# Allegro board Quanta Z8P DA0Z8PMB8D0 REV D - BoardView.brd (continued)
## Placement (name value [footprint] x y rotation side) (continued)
PQ4  AO3404  [SOT23_213-3_3-2]  48.25 89.11 90 top
PQ5  2N7002K  [SOT23_213-3_3-2]  35.24 75.34 90 top
PQ6  TPCA8109  [POWER-5X5-1_27-5P]  233.41 40.21 180 top
PQ7  2N7002K  [SOT23_213-3_3-2]  68.49 30.84 90 top
PQ8  2N7002K  [SOT23_213-3_3-2]  41.8 30 0 top
PQ9  2N7002KDW  [SOT363-2_1-65-6P]  38.43 24.94 180 top
PQ10  *2N7002K  [SOT23_213-3_3-2]  31.77 21.11 90 top
PQ11  AON7410  [DFN-8L-3X3-65-5P-0_9H]  75.81 131.53 270 bottom
PQ12  AON7752  [DFN-8L-3X3-65-5P-0_9H]  80.12 131.27 0 bottom
PQ13  AON6414AL  [POWER-5_2X5_55-1_27-5P]  89.57 131.2 0 bottom
PQ14  AON6752  [POWER-5_2X5_55-1_27-5P]  96.43 131.07 0 bottom
PQ15  *2N7002K  [SOT23_213-3_3-2]  149.9 43.5 180 bottom
PQ16  IMD2AT108  [SC74-2_8-95-6P]  201 37.79 270 bottom
PQ17  TPCA8109  [POWER-5X5-1_27-5P]  69.64 28.08 0 bottom
PQ18  AON7410  [DFN-8L-3X3-65-5P-0_9H]  95.74 28.02 180 bottom
PQ19  AON7752  [DFN-8L-3X3-65-5P-0_9H]  95.74 24.08 270 bottom
PQ20  AON7410  [DFN-8L-3X3-65-5P-0_9H]  51.42 23.07 270 bottom
PQ21  AON7410  [DFN-8L-3X3-65-5P-0_9H]  51.42 19.13 270 bottom
PQ22  VL@AO3415  [SOT23_213-3_3-2]  58.28 116.85 270 top
PQ23  VL@2N7002K  [SOT23_213-3_3-2]  62.22 120.22 0 top
PQ24  VL@DDTC144EUA-7-F  [UMT_213-3-1_3]  65.52 138.13 0 top
PQ25  VL@2N7002K  [SOT23_213-3_3-2]  61.71 137.88 0 top
PR1  *S_6  [S0603]  100.13 137.62 0 top
PR2  *S_6  [S0603]  82.28 137.01 0 top
PR3  100K_1%_4  [R0402]  129.27 135.77 270 top
PR4  *S_4  [S0402]  131.56 133.94 180 top
PR5  2.2_5%_6  [R0603]  96.25 132.8 180 top
PR6  2.61K_1%_4  [R0402]  116.42 130.65 90 top
PR7  VL@0_5%_4  [R0402]  51.43 129.78 90 top
PR8  VL@20K_1%_4  [R0402]  53.68 129.78 90 top
PR9  VL@174K_1%_4  [R0402]  54.7 129.78 270 top
PR10  VL@100K_5%_4  [R0402]  55.74 129.77 90 top
PR11  127K_1%_4  [R0402]  110.81 128.61 270 top
PR12  *S_4  [S0402]  113.96 128.61 270 top
PR13  402_1%_4  [R0402]  115.04 128.61 270 top
PR14  332_1%_4  [R0402]  117.46 128.61 270 top
PR15  *S_6  [S0603]  130.97 128.85 90 top
PR16  2.2_5%_6  [R0603]  74.92 127.59 0 top
PR17  *4.7_5%_6  [R0603]  127.47 127.36 90 top
PR18  63.4K_1%_4  [R0402]  118.86 126.32 180 top
PR19  11K_1%_4  [R0402]  107.54 125.94 0 top
PR20  63.4K_1%_4  [R0402]  118.86 125.18 180 top
PR21  100_1%_4  [R0402]  104 124.54 0 top
PR22  2.61K_1%_4  [R0402]  105.9 124.54 0 top
PR23  499_1%_4  [R0402]  109.59 124.54 0 top
PR24  20_1%_4  [R0402]  118.86 124.03 0 top
PR25  *VL@0_5%_4  [R0402]  57.3 124.2 0 top
PR26  2.55K_1%_4  [R0402]  107.68 123.4 0 top
PR27  169_1%_4  [R0402]  121.02 123.12 0 top
PR28  *VL@0_5%_4  [R0402]  58.67 123.4 270 top
PR29  VL@0_5%_4  [R0402]  57.3 123.24 180 top
PR30  100_1%_4  [R0402]  104.38 122.38 180 top
PR31  10K_1%_4  [R0402]  107.68 122.26 0 top
PR32  27.4K_1%_4  [R0402]  109.59 122.26 0 top
PR33  *S_4  [S0402]  118.86 120.6 180 top
PR35  1M_5%_6  [R0603]  138.8 89.24 0 top
PR36  1M_5%_6  [R0603]  141.59 89.24 180 top
PR37  1M_5%_6  [R0603]  144.39 89.24 180 top
PR38  *100K_1%_6  [R0603]  146.67 88.73 90 top
PR39  22_5%_8  [R0805]  41.01 87.33 270 top
PR40  *4.7_5%_6  [R0603]  140.52 82.35 0 top
PR41  *S_6  [S0603]  46.54 81.67 90 top
PR42  22_5%_8  [R0805]  33.5 72.87 270 top
PR43  *220_5%_8  [R0805]  145.4 40.98 180 top
PR44  0.02_1%_0612  [RC3216]  219.59 34.3 270 top
PR45  *S_4  [S0402]  219.16 31.42 270 top
PR46  *S_4  [S0402]  220.31 31.42 270 top
PR47  *S_4  [S0402]  102.35 31.32 270 top
PR48  100_1%_4  [R0402]  103.75 31.32 90 top
PR49  33K_1%_4  [R0402]  71.4 30.55 0 top
PR50  *100K_5%_4  [R0402]  44.85 30.39 270 top
PR51  10K_5%_4  [R0402]  70.24 29.38 0 top
PR52  *4.7_5%_6  [R0603]  91.51 27.92 0 top
PR53  *0_5%_4  [R0402]  107.43 27.21 0 top
PR54  51K_1%_4  [R0402]  41.8 27.08 90 top
PR55  *S_4  [S0402]  42.95 27.08 90 top
PR56  *10K_5%_4  [R0402]  40.49 26.8 90 top
PR57  *0_5%_4  [R0402]  38.96 26.75 180 top
PR58  20_5%_12  [R1206]  48.03 25.59 90 top
PR59  *S_4  [S0402]  108.34 25.35 270 top
PR60  100K_5%_4  [R0402]  40.53 24.92 270 top
PR61  100K_5%_4  [R0402]  41.8 24.92 90 top
PR62  10K_5%_4  [R0402]  42.87 24.92 270 top
PR63  100K_5%_4  [R0402]  36.5 24.31 90 top
PR64  *S_4  [S0402]  104.51 24.08 90 top
PR65  *S_4  [S0402]  105.65 24.08 90 top
PR66  *0_5%_4  [R0402]  42.57 23.4 180 top
PR67  63.4K_1%_4  [R0402]  39.52 22.64 90 top
PR68  11K_1%_4  [R0402]  40.66 22.64 90 top
PR69  *4.7_5%_6  [R0603]  54.72 20.78 180 top
PR70  *S_4  [S0402]  39.62 20.1 180 top
PR71  *S_6  [S0603]  37.61 19.72 90 top
PR72  *S_6  [S0603]  48.03 19.24 180 top
PR73  100_1%_4  [R0402]  73.77 19.13 90 top
PR74  100_1%_4  [R0402]  74.92 19.13 90 top
PR75  100_1%_4  [R0402]  79.11 19.13 90 top
PR76  *S_4  [S0402]  39.62 19.08 180 top
PR77  *0_5%_4  [R0402]  72.12 19 270 top
PR78  0.01_1%_0612  [RC3216]  62.54 18.12 90 top
PR79  1M_5%_4  [R0402]  73.77 17.23 90 top
PR80  316K_1%_4  [R0402]  39.86 16.06 90 top
PR81  10K_5%_4  [R0402]  41.02 16.17 90 top
PR82  *S_4  [S0402]  63.15 15.06 90 top
PR83  *S_4  [S0402]  62.01 15.04 90 top
PR84  *S_4  [S0402]  93.08 137.33 0 bottom
PR85  *S_4  [S0402]  76.44 136.86 0 bottom
PR86  *S_6  [S0603]  92.67 136.12 0 bottom
PR87  *S_4  [S0402]  129.27 135.77 270 bottom
PR88  10K_1%_4  [R0402]  130.26 135.77 90 bottom
PR89  *S_4  [S0402]  81.88 135.64 180 bottom
PR90  *S_4  [S0402]  99.12 135.34 180 bottom
PR91  3.65K_1%_6  [R0603]  113.1 134.18 0 bottom
PR92  *S_6  [S0603]  76.49 134.93 90 bottom
PR93  499K_1%_4  [R0402]  131.25 134.93 90 bottom
PR94  *S_6  [S0603]  113.12 132.77 0 bottom
PR95  100_1%_4  [R0402]  115.16 132.73 90 bottom
PR96  *S_4  [S0402]  116.95 132.42 0 bottom
PR97  *S_4  [S0402]  118.73 132.42 0 bottom
PR98  150K_1%_4  [R0402]  131.56 133.43 180 bottom
PR99  1K_1%_4  [R0402]  131.56 132.29 0 bottom
PR100  11K_1%_4  [R0402]  116.42 130.65 90 bottom
PR101  1K_1%_4  [R0402]  117.46 130.65 270 bottom
PR102  *S_6  [S0603]  122.03 128.73 180 bottom
PR103  *S_4  [S0402]  110.81 128.61 90 bottom
PR104  *S_4  [S0402]  111.82 128.61 90 bottom
PR105  4.02K_1%_4  [R0402]  112.84 128.61 270 bottom
PR106  *2K_1%_4  [R0402]  113.96 128.61 270 bottom
PR107  301_1%_4  [R0402]  115.04 128.61 270 bottom
PR108  *S_4  [S0402]  118.86 127.34 0 bottom
PR109  10K_1%_4  [R0402]  131.18 128.1 180 bottom
PR110  10K_NTC_4_1%  [R0402]  82.28 127.84 180 bottom
PR111  182_1%_4  [R0402]  109.59 127.08 0 bottom
PR112  *S_4  [S0402]  118.86 126.32 0 bottom
PR113  470K_NTC_4_5%  [R0402]  99.55 126.95 0 bottom
PR114  *S_6  [S0603]  121.4 126.07 180 bottom
PR115  1K_1%_4  [R0402]  107.54 125.94 0 bottom
PR116  10K_NTC_4_1%  [R0402]  99.55 125.43 0 bottom
PR117  1_1%_6  [R0603]  121.37 124.56 0 bottom
PR118  2K_1%_4  [R0402]  109.59 124.54 0 bottom
PR119  *S_4  [S0402]  104.38 123.53 180 bottom
PR120  2K_1%_4  [R0402]  109.59 123.4 0 bottom
PR121  3.65K_1%_6  [R0603]  99.68 124.03 0 bottom
PR122  86.6_1%_4  [R0402]  121.02 123.12 0 bottom
PR123  95.3_1%_4  [R0402]  118.86 122.71 180 bottom
PR124  *S_4  [S0402]  104.38 122.38 180 bottom
PR125  *S_4  [S0402]  131.18 122.64 180 bottom
PR126  *S_6  [S0603]  99.68 122.59 0 bottom
PR127  *S_4  [S0402]  118.86 121.75 180 bottom
PR128  97.6K_1%_4  [R0402]  109.59 121.11 0 bottom
PR129  10K_1%_4  [R0402]  121.02 120.73 0 bottom
PR130  *S_4  [S0402]  118.86 120.6 180 bottom
PR131  *10K_1%_4  [R0402]  119.24 119.59 0 bottom
PR132  *S_4  [S0402]  113.55 119.46 180 bottom
PR133  *S_4  [S0402]  117.33 119.59 180 bottom
PR136  *S_4  [S0402]  123.32 115.55 180 bottom
PR137  *S_4  [S0402]  123.32 114.43 180 bottom
PR138  *S_4  [S0402]  123.32 113.37 0 bottom
PR141  7.5K_1%_4  [R0402]  130.03 111.13 90 bottom
PR142  *S_4  [S0402]  126.61 110.75 0 bottom
PR143  10K_1%_4  [R0402]  128.51 109.73 0 bottom
PR144  100K_1%_4  [R0402]  124.09 108.41 270 bottom
PR145  *S_4  [S0402]  125.11 108.41 270 bottom
PR146  *S_4  [S0402]  118.13 108.16 180 bottom
PR147  10_5%_6  [R0603]  130.8 106 270 bottom
PR148  *2.2_5%_6  [R0603]  126.22 104.22 90 bottom
PR149  100K_1%_4  [R0402]  131.69 92.16 90 bottom
PR150  *S_6  [S0603]  130.42 90.76 90 bottom
PR151  *S_4  [S0402]  133.46 90.76 90 bottom
PR152  *S_4  [S0402]  131.69 90.25 270 bottom
PR153  24K_1%_4  [R0402]  112.88 89.41 270 bottom
PR154  16K_1%_4  [R0402]  133.46 88.85 90 bottom
PR155  15K_1%_4  [R0402]  133.46 86.95 90 bottom
PR156  *S_4  [S0402]  119.93 85.44 180 bottom
PR157  *S_4  [S0402]  144.11 85.35 270 bottom
PR158  499K_1%_4  [R0402]  145.12 85.32 90 bottom
PR159  150_1%_4  [R0402]  117.83 84.22 270 bottom
PR160  100K_1%_4  [R0402]  46.97 84.1 90 bottom
PR161  *S_4  [S0402]  47.93 84.1 90 bottom
PR162  150K_1%_4  [R0402]  145.15 83.9 180 bottom
PR163  *S_4  [S0402]  132.32 83.14 90 bottom
PR164  *S_4  [S0402]  145.53 82.63 180 bottom
PR165  *S_4  [S0402]  46.97 82.2 270 bottom
PR166  30K_1%_4  [R0402]  47.93 82.2 90 bottom
PR167  15K_1%_4  [R0402]  48.89 82.2 270 bottom
PR168  1K_1%_4  [R0402]  145.53 81.49 0 bottom
PR169  *S_6  [S0603]  138.92 79.89 180 bottom
PR170  100K_5%_4  [R0402]  49.14 75.01 90 bottom
PR171  *S_4  [S0402]  145.15 69.55 180 bottom
PR172  *S_4  [S0402]  144.39 61.95 270 bottom
PR173  *S_4  [S0402]  145.4 61.95 270 bottom
PR174  *S_4  [S0402]  146.42 61.95 90 bottom
PR179  *S_4  [S0402]  137.92 51.12 180 bottom
PR180  *S_8  [S0805]  132.34 50.11 90 bottom
PR181  *S_8  [S0805]  146.37 48.75 270 bottom
PR182  *S_4  [S0402]  131.25 46.31 180 bottom
PR183  30K_1%_4  [R0402]  146.04 46.11 0 bottom
PR184  100K_5%_4  [R0402]  134.26 45.92 90 bottom
PR185  34K_1%_4  [R0402]  144.49 45.7 90 bottom
PR186  100K_5%_4  [R0402]  134.26 43.99 270 bottom
PR187  220K_1%_4  [R0402]  198.55 36.94 180 bottom
PR188  220K_1%_4  [R0402]  198.55 35.98 0 bottom
PR189  *S_4  [S0402]  201.39 34.9 180 bottom
PR190  *S_4  [S0402]  104.84 31.3 270 bottom
PR191  10K_1%_4  [R0402]  106.67 30.21 180 bottom
PR192  10K_1%_4  [R0402]  107.43 29.24 180 bottom
PR193  *S_4  [S0402]  107.43 28.28 0 bottom
PR194  499K_1%_4  [R0402]  107.43 27.21 0 bottom
PR195  2.2_5%_6  [R0603]  99.13 27.06 180 bottom
PR196  *S_4  [S0402]  107.43 25.87 0 bottom
PR197  100K_1%_4  [R0402]  107.82 24.53 270 bottom
PR198  *0_5%_4  [R0402]  105.65 24.08 90 bottom
PR199  340K_1%_4  [R0402]  103.36 24.08 90 bottom
PR200  100K_1%_4  [R0402]  39.55 17.93 180 bottom
PR201  *100K_5%_4  [R0402]  39.52 16.89 180 bottom
PR202  10_5%_6  [R0603]  43.42 15.83 270 bottom
PR203  7.5_5%_6  [R0603]  41.9 15.83 270 bottom
PR204  VL@0_5%_8  [R0805]  59.42 113.75 0 top
PR205  VL@100K_1%_4  [R0402]  56.88 113.24 0 top
PR206  VL@10K_5%_4  [R0402]  60.69 122.38 90 top
PR207  VL@0_5%_4  [R0402]  60.82 117.68 270 top
PR208  VL@0_5%_4  [R0402]  68.44 135.73 270 top
PR209  VL@1M_5%_6  [R0603]  66.79 135.08 270 top
PR210  VL@22_5%_8  [R0805]  61.58 134.83 0 top
PR211  VL@1M_5%_6  [R0603]  65.26 135.08 90 top
PR212  *VL@100K_1%_6  [R0603]  68.44 138.13 270 top
PU1  VL@TPS61087DRCR  [QFN10-3X3-5-16P]  53.08 126.42 180 top
PU2  BQ24737RGRR  [PVQFN20-3_5X3_5-5-25P]  43.2 19.97 180 top
PU3  ISL95808HRZ-T  [DFN8-2X2-5-9P-ISL6208BCRZ]  79.23 136.1 90 bottom
PU4  ISL95808HRZ-T  [DFN8-2X2-5-9P-ISL6208BCRZ]  96.13 135.89 90 bottom
PU5  SY8286BRAC  [QFN20-3X3-45-21P]  128.26 132.29 90 bottom
PU6  ISL95859AHRTZ-T  [QFN40-5X5-4-41P-ISL95859]  114.16 123.27 180 bottom
PU7  AOZ1331DI  [SON14-3X2-4-15P-SMT]  117.21 114.38 270 bottom
PU8  M5671RE1U  [DFN10-3X3-5-11P-G5318]  127.88 107.27 90 bottom
PU9  TMP708AIDBVR  [SOT23-5-2_8-95-5P-G708]  115.06 88.02 90 bottom
PU10  G5719CTB1U  [SOT23-6-2_8-95-6P-G5126TB1U]  131.18 86.57 270 bottom
PU11  SY8288CRAC  [QFN20-3X3-45-21P]  142.35 81.87 90 bottom
PU12  G5719CTB1U  [SOT23-6-2_8-95-6P-G5126TB1U]  46.14 78.84 270 bottom
PU13  AOZ1331DI  [SON14-3X2-4-15P-SMT]  145.02 55.96 0 bottom
PU14  G9661MF11U  [SOP8-6-1_27-9P-G5795F11U]  139.18 46.94 90 bottom
PU15  RT8231BGQW  [WQFN20-3X3-4-21P]  103.52 27.61 0 bottom
Q1  PJA138K  [SOT23_213-3_3-2]  65.09 131.65 180 top
Q2  DDTC144EUA-7-F  [UMT_213-3-1_3]  48.12 112.73 90 top
Q3  2N7002KDW  [SOT363-2_1-65-6P]  46.98 106.63 180 top
Q4  2N7002KDW  [SOT363-2_1-65-6P]  93.95 97.54 0 top
Q5  2N7002K  [SOT23_213-3_3-2]  60.82 85.81 180 top
Q6  TPC@PJA138K  [SOT23_213-3_3-2]  28.22 82.2 180 top
Q7  TPC@AON7401  [POWER-3_3X3_3-65-5P-SMT]  24.52 82.1 270 top
Q8  TPC@PJA138K  [SOT23_213-3_3-2]  28.22 78.49 90 top
Q9  PJA138K  [SOT23_213-3_3-2]  20.08 75.53 270 top
Q10  SSM6N43FU  [SC70-2_1-65-6P]  27.57 73.43 0 top
Q11  2N7002KDW  [SOT363-2_1-65-6P]  51.65 71.33 90 top
Q12  *PJA138K  [SOT23_213-3_3-2]  23.2 71.4 270 top
Q13  2N7002K  [SOT23_213-3_3-2]  18.41 57.63 180 top
Q14  YB8251ST23  [SOT23_213-3_3-2]  2.5 56 0 top
Q15  SSM6N43FU  [SC70-2_1-65-6P]  33.51 26.88 0 top
Q16  EJ@METR3904-G  [SOT23_213-3_3-2]  212.92 34.07 0 top
Q17  2N7002K  [SOT23_213-3_3-2]  129.59 33.76 270 top
Q19  GS@2N7002KDW  [SOT363-2_1-65-6P]  163.82 29.16 90 top
Q20  2N7002KDW  [SOT363-2_1-65-6P]  107.4 18.62 270 top
Q21  SSM6N43FU  [SC70-2_1-65-6P]  114.32 18.14 180 top
Q22  KBL@PJA3413  [SOT23_213-3_3-2]  230.24 17.35 0 top
Q23  KBL@DDTC144EUA-7-F  [UMT_213-3-1_3]  230.49 14.03 0 top
Q24  *SSM6N43FU  [SC70-2_1-65-6P]  105.14 108.41 90 bottom
Q25  *SSM6N43FU  [SC70-2_1-65-6P]  108.7 108.41 90 bottom
Q26  SSM6N43FU  [SC70-2_1-65-6P]  76.44 104.48 90 bottom
Q27  SSM6N43FU  [SC70-2_1-65-6P]  78.73 104.48 90 bottom
Q28  SSM6N43FU  [SC70-2_1-65-6P]  81.16 104.47 90 bottom
Q29  2N7002KDW  [SOT363-2_1-65-6P]  66.53 95.23 90 bottom
Q30  2N7002K  [SOT23_213-3_3-2]  53.09 88.48 180 bottom
Q31  PJA138K  [SOT23_213-3_3-2]  125.56 34.7 0 bottom
Q32  *PJA138K  [SOT23_213-3_3-2]  193.87 34.13 180 bottom
Q33  *SSM6N43FU  [SC70-2_1-65-6P]  131 32.31 0 bottom
Q34  EJ@PMST3904  [UMT_213-3-1_3]  193.82 23.17 90 bottom
Q35  *SSM6N43FU  [SC70-2_1-65-6P]  167.63 32.34 180 top
Q36  *PSD@SSM6N43FU  [SC70-2_1-65-6P]  30.75 96.5 90 top
R1  33_5%_4  [R0402]  60.31 132.29 90 top
R2  100K_5%_4  [R0402]  61.45 132.29 90 top
R3  0_5%_4  [R0402]  61.08 125.19 0 top
R4  *0_5%_4  [R0402]  61.08 124.23 0 top
R5  NVL@0_5%_6  [R0603]  53.07 114.38 90 top
R6  VL@0_5%_6  [R0603]  51.55 111.84 180 top
R7  10K_5%_4  [R0402]  47.61 108.41 0 top
R8  100K_5%_4  [R0402]  50.15 108.41 180 top
R9  *S_4  [S0402]  50.15 107.27 0 top
R10  *S_4  [S0402]  52.06 107.27 0 top
R11  10K_5%_4  [R0402]  43.42 107.02 270 top
R12  EJ@75_1%_8  [R0805]  27.69 105.87 90 top
R13  EJ@75_1%_8  [R0805]  30.23 105.87 90 top
R14  EJ@75_1%_8  [R0805]  34.07 105.87 90 top
R15  EJ@75_1%_8  [R0805]  36.69 105.87 90 top
R16  *4.7K_5%_4  [R0402]  74.59 101.65 0 top
R17  1K_1%_4  [R0402]  76.83 100.22 270 top
R18  *4.7K_5%_4  [R0402]  73.79 100.22 270 top
R19  *10K_5%_4  [R0402]  75.85 100.22 90 top
R20  4.7K_5%_4  [R0402]  74.8 100.22 90 top
R21  10K_5%_4  [R0402]  90.08 100.16 270 top
R22  10K_5%_4  [R0402]  91.85 100 0 top
R23  *10K_5%_4  [R0402]  80.02 99.87 270 top
R24  *S_4  [S0402]  81.09 99.86 270 top
R25  10K_5%_4  [R0402]  86.24 99.65 90 top
R26  *10K_5%_4  [R0402]  72.37 99.59 0 top
R27  *4.7K_5%_4  [R0402]  85.25 99.58 270 top
R28  *4.7K_5%_4  [R0402]  83.51 99.37 180 top
R29  4.7K_5%_4  [R0402]  72.36 98.57 180 top
R30  10K_5%_4  [R0402]  73.79 98.46 270 top
R31  10K_5%_4  [R0402]  79.62 98.27 0 top
R32  10K_5%_4  [R0402]  83.82 98.02 270 top
R33  10K_5%_4  [R0402]  85.28 97.83 270 top
R34  200_1%_4  [R0402]  89.43 97.59 90 top
R35  10K_5%_4  [R0402]  71.61 97.57 180 top
R36  4.7K_5%_4  [R0402]  79.39 97.31 0 top
R37  402_1%_4  [R0402]  100.55 97.14 180 top
R38  4.7K_5%_4  [R0402]  66.46 96.63 180 top
R39  4.7K_5%_4  [R0402]  71.61 96.55 0 top
R40  150_1%_4  [R0402]  96.45 96.14 180 top
R41  10K_5%_4  [R0402]  71.61 95.53 0 top
R42  60.4_1%_4  [R0402]  96.44 95.11 0 top
R43  10K_5%_4  [R0402]  71.61 94.52 0 top
R44  150_1%_4  [R0402]  93.64 94.41 180 top
R45  4.7K_5%_4  [R0402]  66.81 94.19 0 top
R47  *0_5%_4  [R0402]  25.29 93.71 0 top
R48  TPC@100K_1%_4  [R0402]  26.63 93.55 90 top
R49  *S_4  [S0402]  27.67 93.55 270 top
R50  TPC@100K_5%_4  [R0402]  28.69 93.55 90 top
R51  TPC@100K_5%_4  [R0402]  29.83 93.55 90 top
R52  33_5%_4  [R0402]  71.61 93.43 180 top
R54  10K_5%_4  [R0402]  87.44 92.44 270 top
R55  10K_5%_4  [R0402]  71.61 92.41 180 top
R56  TPC@10K_5%_4  [R0402]  30.29 92.05 0 top
R57  4.7K_5%_4  [R0402]  71.61 91.39 180 top
R58  200_1%_4  [R0402]  76.23 90.57 90 top
R59  10K_5%_4  [R0402]  71.61 90.38 180 top
R60  10M_5%_4  [R0402]  69.05 89.69 270 top
R61  10_5%_4  [R0402]  74.73 89.32 0 top
R62  330K_5%_4  [R0402]  82.88 88.08 180 top
R63  EC@20K_1%_4  [R0402]  54.35 87.62 180 top
R64  137_1%_4  [R0402]  98.96 86.82 180 top
R65  TPC@100K_5%_4  [R0402]  24.24 86.57 180 top
R66  10K_5%_4  [R0402]  58.41 86.19 90 top
R67  *100K_5%_4  [R0402]  67.4 86.14 180 top
R68  *S_4  [S0402]  30.96 86.06 270 top
R69  *TPC@100K_5%_4  [R0402]  31.92 86.06 270 top
R70  *10K_5%_4  [R0402]  32.88 86.06 270 top
R71  1K_1%_4  [R0402]  69.58 86.06 180 top
R72  10_5%_4  [R0402]  74.74 86.02 0 top
R73  200_1%_4  [R0402]  72.98 85.84 180 top
R74  402_1%_4  [R0402]  104.82 85.83 180 top
R75  113_1%_4  [R0402]  98.19 85.53 180 top
R76  TPC@100K_5%_4  [R0402]  24.46 85.18 270 top
R77  TPC@100K_5%_4  [R0402]  25.93 85.18 270 top
R78  *S_4  [S0402]  27.6 85.17 270 top
R79  *TPC@100K_5%_4  [R0402]  28.69 85.17 270 top
R80  TPC@100K_5%_4  [R0402]  29.65 85.17 270 top
R81  20K_1%_4  [R0402]  69.58 85.04 180 top
R82  *100K_5%_4  [R0402]  69.58 84.03 180 top
R83  10_5%_4  [R0402]  75.42 84.03 0 top
R84  *S_6  [S0603]  63.48 83.74 180 top
R85  10K_5%_4  [R0402]  69.58 83.01 0 top
R86  *S_6  [S0603]  67.17 82.34 270 top
R87  150_1%_4  [R0402]  102.53 82.11 180 top
R88  *S_4  [S0402]  69.58 82 180 top
R89  105_1%_4  [R0402]  90.15 81.79 180 top
R90  2K_1%_4  [R0402]  69.58 80.98 180 top
R91  105_1%_4  [R0402]  90.39 80.45 90 top
R92  2K_1%_4  [R0402]  69.58 79.96 180 top
R93  PSD@10K_5%_4  [R0402]  35.04 97.49 180 top
R94  TPC@100K_5%_4  [R0402]  25.23 79.51 180 top
R95  33_5%_4  [R0402]  69.58 78.95 180 top
R96  TPC@10K_5%_4  [R0402]  31 78.74 0 top
R97  TPC@10K_5%_4  [R0402]  25.23 78.55 180 top
R98  33_5%_4  [R0402]  69.58 77.78 180 top
R99  *S_4  [S0402]  21.35 77.3 270 top
R100  *0_5%_4  [R0402]  22.31 77.42 270 top
R101  10_5%_4  [R0402]  90.25 77 90 top
R102  10_5%_4  [R0402]  87.63 75.69 270 top
R103  *2.2K_5%_4  [R0402]  26.76 75.05 180 top
R104  *S_4  [S0402]  28.61 75.05 180 top
R105  1K_1%_4  [R0402]  91.27 74.9 270 top
R106  1K_1%_4  [R0402]  89.93 74.7 0 top
R107  *0_5%_4  [R0402]  19.58 72.09 270 top
R108  *S_4  [S0402]  20.83 72.09 270 top
R109  *0_5%_4  [R0402]  30.26 72.04 270 top
R110  2.2K_5%_4  [R0402]  17.77 71.97 90 top
R111  *0_5%_4  [R0402]  24.12 68.97 0 top
R112  *2.2K_5%_4  [R0402]  27.07 71.81 180 top
R113  *S_4  [S0402]  28.79 71.71 180 top
R114  *0_5%_4  [R0402]  19.58 70.31 270 top
R115  *S_4  [S0402]  20.83 70.31 270 top
R116  2.2K_5%_4  [R0402]  17.92 70.18 270 top
R117  *12.4K_1%_4  [R0402]  29.89 70.06 270 top
R118  *10K_5%_4  [R0402]  30.85 70.06 270 top
R119  *10K_5%_4  [R0402]  26.5 70.18 270 top
R120  *0_5%_4  [R0402]  27.46 70.05 270 top
R121  *0_5%_4  [R0402]  28.42 70.05 270 top
R122  470_1%_4  [R0402]  21.31 68.79 180 top
R123  *0_5%_4  [R0402]  19.12 68.71 180 top
R125  *0_5%_4  [R0402]  19.12 67.75 180 top
R126  470_1%_4  [R0402]  21.32 67.63 180 top
R129  470_1%_4  [R0402]  21.32 66.67 180 top
R130  *0_5%_4  [R0402]  19.12 66.55 180 top
R132  *0_5%_4  [R0402]  19.12 65.59 180 top
R133  470_1%_4  [R0402]  21.32 65.46 180 top
R134  470_1%_4  [R0402]  21.32 64.5 180 top
R135  *0_5%_4  [R0402]  19.12 64.38 180 top
R137  *0_5%_4  [R0402]  19.12 63.42 180 top
R138  470_1%_4  [R0402]  21.32 63.3 180 top
R139  470_1%_4  [R0402]  21.32 62.34 180 top
R140  *0_5%_4  [R0402]  19.12 62.21 180 top
R142  *0_5%_4  [R0402]  19.12 61.25 180 top
R143  470_1%_4  [R0402]  21.32 61.13 180 top
R144  3.65K_1%_4  [R0402]  47.87 59.64 0 top
R145  3.65K_1%_4  [R0402]  50.41 59.64 0 top
R146  3.65K_1%_4  [R0402]  47.87 58.63 180 top
R147  3.65K_1%_4  [R0402]  50.41 58.63 180 top
R148  3.65K_1%_4  [R0402]  118.35 56.6 180 top
R149  240_1%_4  [R0402]  64.91 56.52 90 top
R150  3.65K_1%_4  [R0402]  118.35 55.58 0 top
R151  2.2_5%_6  [R0603]  18.19 55.05 180 top
R152  1K_1%_4  [R0402]  50.41 54.56 180 top
R153  *S_4  [S0402]  22.85 52.94 180 top
R154  80.6_1%_4  [R0402]  66.38 52.88 270 top
R155  240_1%_4  [R0402]  100.6 52.81 90 top
R156  80.6_1%_4  [R0402]  101.59 52.79 270 top
R157  *S_4  [S0402]  22.85 51.92 180 top
R158  0_5%_4  [R0402]  22.83 50.96 180 top
R159  240_1%_4  [R0402]  117.84 50.88 270 top
R160  1K_1%_4  [R0402]  85.89 50.45 270 top
R161  0_5%_4  [R0402]  22.83 49.95 180 top
R162  240_1%_4  [R0402]  82.79 49.74 270 top
R163  *S_6  [S0603]  162.14 40.95 180 top
R164  3.65K_1%_4  [R0402]  118.35 46.18 0 top
R165  *S_4  [S0402]  27.76 45.86 180 top
R166  3.65K_1%_4  [R0402]  118.35 45.17 180 top
R167  *S_4  [S0402]  27.76 44.84 180 top
R168  10K_5%_4  [R0402]  32.09 42.45 0 top
R169  *4.7K_5%_4  [R0402]  208.35 41.48 270 top
R170  *4.7K_5%_4  [R0402]  210.17 41.48 90 top
R171  *4.7K_5%_4  [R0402]  207.39 41.36 90 top
R172  *4.7K_5%_4  [R0402]  206.03 41.09 0 top
R173  2.49K_1%_4  [R0402]  24.36 41.24 90 top
R174  *S_6  [S0603]  34.78 40.21 270 top
R175  CB@0_5%_4  [R0402]  210.53 40.14 180 top
R176  CB@4.7K_5%_4  [R0402]  136.55 39.21 0 top
R177  CB@4.7K_5%_4  [R0402]  138.42 39.2 180 top
R178  80.6_1%_4  [R0402]  61.2 39.07 270 top
R179  80.6_1%_4  [R0402]  62.22 39.07 270 top
R180  80.6_1%_4  [R0402]  63.23 39.07 270 top
R181  80.6_1%_4  [R0402]  64.25 39.07 270 top
R182  80.6_1%_4  [R0402]  65.26 39.07 270 top
R183  80.6_1%_4  [R0402]  66.28 39.07 270 top
R184  80.6_1%_4  [R0402]  67.3 39.07 270 top
R185  80.6_1%_4  [R0402]  68.31 39.07 270 top
R186  80.6_1%_4  [R0402]  69.33 39.07 270 top
R187  80.6_1%_4  [R0402]  70.34 39.07 270 top
R188  80.6_1%_4  [R0402]  71.36 39.07 270 top
R189  80.6_1%_4  [R0402]  72.38 39.07 270 top
R190  80.6_1%_4  [R0402]  95.36 39.07 270 top
R191  80.6_1%_4  [R0402]  96.38 39.07 270 top
R192  80.6_1%_4  [R0402]  97.4 39.07 270 top
R193  80.6_1%_4  [R0402]  98.41 39.07 270 top
R194  80.6_1%_4  [R0402]  99.43 39.07 270 top
R195  80.6_1%_4  [R0402]  100.44 39.07 270 top
R196  80.6_1%_4  [R0402]  101.46 39.07 270 top
R197  80.6_1%_4  [R0402]  102.48 39.07 270 top
R198  80.6_1%_4  [R0402]  103.49 39.07 270 top
R199  80.6_1%_4  [R0402]  104.51 39.07 270 top
R200  80.6_1%_4  [R0402]  105.52 39.07 270 top
R201  80.6_1%_4  [R0402]  106.54 39.07 270 top
R202  *10K_5%_4  [R0402]  133.03 38.71 0 top
R203  CB@0_5%_4  [R0402]  210.53 38.61 180 top
R204  33_5%_4  [R0402]  135.68 38.15 0 top
R205  2.2_5%_6  [R0603]  142.35 37.55 90 top
R206  4.7K_5%_4  [R0402]  140.96 38.05 270 top
R207  CB@10K_5%_4  [R0402]  133.97 36.53 270 top
R208  33_5%_4  [R0402]  132.05 36.49 270 top
R209  *S_6  [S0603]  37.68 36.46 180 top
R210  100K_5%_4  [R0402]  140.32 35.01 270 top
R211  4.7K_5%_4  [R0402]  139.94 38.05 270 top
R212  10K_5%_4  [R0402]  141.5 34.75 270 top
R213  10K_5%_4  [R0402]  144.31 34.75 270 top
R214  33_5%_4  [R0402]  145.53 34.75 270 top
R215  100K_5%_4  [R0402]  135.98 34.63 270 top
R216  *4.7K_5%_4  [R0402]  204.6 34.41 0 top
R217  4.7K_5%_4  [R0402]  201.75 34.37 90 top
R218  *4.7K_5%_4  [R0402]  202.81 34.37 270 top
R219  *4.7K_5%_4  [R0402]  206.23 33.99 90 top
R220  *4.7K_5%_4  [R0402]  207.25 33.99 90 top
R221  *10K_5%_4  [R0402]  153.02 33.74 180 top
R222  EJ@1K_1%_4  [R0402]  215.25 33.65 90 top
R223  EJ@10K_5%_4  [R0402]  216.21 33.65 90 top
R224  1K_1%_4  [R0402]  37.21 33.55 0 top
R225  15K_1%_4  [R0402]  35.17 33.16 90 top
R226  10K_5%_4  [R0402]  36.57 32.59 0 top
R227  *S_4  [S0402]  205.13 32.3 90 top
R228  *10K_5%_4  [R0402]  196.53 32.06 270 top
R229  EJ@10K_5%_4  [R0402]  211.98 31.58 0 top
R230  *S_4  [S0402]  214.36 31.58 0 top
R231  GS@10K_5%_4  [R0402]  163.82 31.55 90 top
R232  1K_1%_4  [R0402]  195.11 31.32 180 top
R233  100K_5%_4  [R0402]  130.61 31.42 0 top
R234  *S_6  [S0603]  22.67 31.42 180 top
R235  *S_4  [S0402]  209.89 31.41 0 top
R236  *S_4  [S0402]  153.02 30.43 0 top
R237  *S_4  [S0402]  129.32 30.06 0 top
R238  *S_4  [S0402]  193.96 29.79 0 top
R239  *S_4  [S0402]  209.26 29.47 180 top
R240  *S_4  [S0402]  196.43 28.63 0 top
R241  *S_4  [S0402]  114.64 27.85 270 top
R242  w/o GS@0_5%_4  [R0402]  226.38 27.79 270 top
R243  22_5%_4  [R0402]  196.43 27.61 180 top
R244  62_1%_4  [R0402]  208.14 27.03 0 top
R245  20K_1%_4  [R0402]  188.07 26.75 90 top
R246  20K_1%_4  [R0402]  190.49 26.75 90 top
R247  *S_4  [S0402]  18.02 25.5 180 top
R248  2.2_5%_6  [R0603]  124.17 25.32 180 top
R249  33_5%_4  [R0402]  194.14 24.82 180 top
R250  33_5%_4  [R0402]  151.83 24.92 0 top
R251  100K_5%_4  [R0402]  210.04 24.59 0 top
R252  CB@0_5%_8  [R0805]  231.56 24.18 0 top
R253  33_5%_4  [R0402]  154.52 23.84 270 top
R254  100K_5%_4  [R0402]  150.1 23.56 180 top
R255  20K_1%_4  [R0402]  194.14 21.77 0 top
R256  100K_1%_4  [R0402]  199.12 21.42 90 top
R257  200K_1%_4  [R0402]  200.14 21.42 90 top
R258  10K_5%_4  [R0402]  113.87 21.13 90 top
R259  10K_5%_4  [R0402]  114.83 21.13 90 top
R260  EJ@0_5%_8  [R0805]  232.17 21.11 90 top
R261  10K_5%_4  [R0402]  107.43 20.91 0 top
R262  10K_5%_4  [R0402]  195.92 20.63 0 top
R263  *S_4  [S0402]  118.09 20.59 0 top
R264  2K_1%_4  [R0402]  114.12 19.79 180 top
R265  10K_5%_4  [R0402]  149.11 19.46 270 top
R266  KBL@10K_5%_4  [R0402]  232.65 16.85 90 top
R267  10K_5%_4  [R0402]  107.66 16.7 0 top
R268  2K_1%_4  [R0402]  114.03 16.44 180 top
R269  33_5%_4  [R0402]  149.69 15.82 90 top
R270  *S_4  [S0402]  218.1 15.06 270 top
R271  *S_4  [S0402]  219.11 15.06 270 top
R272  *S_4  [S0402]  220.07 14.55 270 top
R273  *S_4  [S0402]  221.09 14.55 270 top
R274  *0_5%_6  [R0603]  63.24 129.28 0 bottom
R275  *S_6  [S0603]  64.55 127.87 0 bottom
R276  *S_4  [S0402]  65.44 125.94 0 bottom
R277  *S_4  [S0402]  65.05 124.44 0 bottom
R278  *100K_5%_4  [R0402]  63.11 122.41 0 bottom
R279  *100K_5%_4  [R0402]  63.11 121.14 0 bottom
R280  *S_4  [S0402]  63.23 110.43 0 bottom
R281  100K_5%_4  [R0402]  66.18 110.01 180 bottom
R282  10K_5%_4  [R0402]  90.45 109.05 90 bottom
R283  10K_5%_4  [R0402]  91.59 109.05 90 bottom
R284  10K_5%_4  [R0402]  92.55 109.05 90 bottom
R285  10K_5%_4  [R0402]  93.7 109.05 90 bottom
R286  10K_5%_4  [R0402]  94.66 109.05 90 bottom
R287  *10K_5%_4  [R0402]  95.8 109.05 90 bottom
R288  10K_5%_4  [R0402]  96.76 109.05 90 bottom
R289  *10K_5%_4  [R0402]  106.79 107.4 270 bottom
R290  *10K_5%_4  [R0402]  90.45 107.14 90 bottom
R291  *10K_5%_4  [R0402]  91.59 107.14 90 bottom
R292  *10K_5%_4  [R0402]  92.55 107.14 90 bottom
R293  *10K_5%_4  [R0402]  93.7 107.14 90 bottom
R294  *10K_5%_4  [R0402]  94.66 107.14 90 bottom
R295  10K_5%_4  [R0402]  95.8 107.14 90 bottom
R296  *10K_5%_4  [R0402]  96.76 107.14 90 bottom
R297  10K_5%_4  [R0402]  78.95 107.08 0 bottom
R298  10K_5%_4  [R0402]  81.38 107.07 0 bottom
R299  10K_5%_4  [R0402]  76.71 107.07 0 bottom
R300  10K_5%_4  [R0402]  102.98 107.4 90 bottom
R301  200K_1%_4  [R0402]  99.81 105.62 180 bottom
R302  33_5%_4  [R0402]  70.59 104.28 270 bottom
R303  51_5%_4  [R0402]  98.32 103.75 270 bottom
R304  100_1%_4  [R0402]  99.28 103.75 270 bottom
R305  51_5%_4  [R0402]  100.24 103.75 270 bottom
R306  100_1%_4  [R0402]  101.2 103.75 270 bottom
R307  100_1%_4  [R0402]  102.16 103.75 270 bottom
R308  *10K_5%_4  [R0402]  93.39 103.72 90 bottom
R309  *10K_5%_4  [R0402]  92.43 103.72 270 bottom
R310  *4.7K_5%_4  [R0402]  82.78 103.71 270 bottom
R311  *4.7K_5%_4  [R0402]  83.74 103.71 270 bottom
R312  4.7K_5%_4  [R0402]  84.7 103.71 270 bottom
R313  10K_5%_4  [R0402]  85.71 103.71 90 bottom
R314  *10K_5%_4  [R0402]  86.67 103.71 270 bottom
R315  *10K_5%_4  [R0402]  87.63 103.71 270 bottom
R316  *10K_5%_4  [R0402]  88.59 103.71 270 bottom
R317  *10K_5%_4  [R0402]  89.55 103.71 270 bottom
R318  10K_5%_4  [R0402]  90.51 103.71 270 bottom
R319  *10K_5%_4  [R0402]  91.47 103.71 270 bottom
R320  *10K_5%_4  [R0402]  94.35 103.71 270 bottom
R321  *GS@10K_5%_4  [R0402]  95.49 103.71 90 bottom
R322  *51_5%_4  [R0402]  96.89 103.21 180 bottom
R323  169_1%_4  [R0402]  105.02 103.71 90 bottom
R324  68_1%_4  [R0402]  105.98 103.71 90 bottom
R325  *S_4  [S0402]  59.93 102.98 180 bottom
R326  *3.3K_5%_4  [R0402]  69.56 102.8 0 bottom
R327  10K_5%_4  [R0402]  73.27 102.7 270 bottom
R328  10K_5%_4  [R0402]  74.28 102.7 270 bottom
R329  220_5%_4  [R0402]  103.6 102.67 0 bottom
R330  10K_5%_4  [R0402]  95 102.31 0 bottom
R331  *S_4  [S0402]  57.17 102.22 180 bottom
R332  10K_5%_4  [R0402]  76.44 102.06 180 bottom
R333  PSD@0_5%_4  [R0402]  41.92 101.99 180 bottom
R334  4.7K_5%_4  [R0402]  81.67 101.82 90 bottom
R335  51_5%_4  [R0402]  97.27 101.82 270 bottom
R336  10K_5%_4  [R0402]  78.21 101.71 90 bottom
R337  10K_5%_4  [R0402]  80.22 101.71 90 bottom
R338  *10K_5%_4  [R0402]  90.51 101.7 270 bottom
R339  10K_5%_4  [R0402]  88.59 101.69 270 bottom
R340  10K_5%_4  [R0402]  89.55 101.69 270 bottom
R341  10K_5%_4  [R0402]  93.53 101.69 270 bottom
R342  10K_5%_4  [R0402]  92.43 101.69 90 bottom
R343  10K_5%_4  [R0402]  82.78 101.68 90 bottom
R344  10K_5%_4  [R0402]  83.74 101.68 90 bottom
R345  *10K_5%_4  [R0402]  84.7 101.68 90 bottom
R346  10K_5%_4  [R0402]  85.71 101.68 270 bottom
R347  10K_5%_4  [R0402]  86.67 101.68 270 bottom
R348  10K_5%_4  [R0402]  87.63 101.68 270 bottom
R349  10K_5%_4  [R0402]  91.47 101.68 90 bottom
R350  *10K_5%_4  [R0402]  95 101.35 180 bottom
R351  PSD@0_5%_4  [R0402]  41.92 100.85 180 bottom
R352  3.3K_5%_4  [R0402]  69.58 100.74 0 bottom
R353  *S_4  [S0402]  56.04 100.51 90 bottom
R354  3.3K_5%_4  [R0402]  69.58 99.78 0 bottom
R355  *EC@20K_1%_4  [R0402]  58.03 99.62 180 bottom
R356  10K_5%_4  [R0402]  69.58 98.63 180 bottom
R357  EC@100K_5%_4  [R0402]  57.21 98.43 0 bottom
R358  PSD@0_5%_4  [R0402]  45.74 97.92 270 bottom
R359  PSD@0_5%_4  [R0402]  46.89 97.92 270 bottom
R360  *10K_5%_4  [R0402]  69.58 97.62 180 bottom
R361  SSD@0_5%_4  [R0402]  45.74 97.15 90 bottom
R362  SSD@0_5%_4  [R0402]  46.89 97.15 90 bottom
R363  *4.7K_5%_4  [R0402]  69.58 96.6 0 bottom
R364  10K_5%_4  [R0402]  71.49 96.6 0 bottom
R365  1K_1%_4  [R0402]  64.35 96.22 0 bottom
R366  10K_5%_4  [R0402]  69.58 95.59 0 bottom
R367  10K_5%_4  [R0402]  71.49 95.59 180 bottom
R368  1K_1%_4  [R0402]  64.61 93.8 0 bottom
R369  20_1%_4  [R0402]  69.38 93.58 0 bottom
R370  20_1%_4  [R0402]  69.38 92.56 0 bottom
R371  20_1%_4  [R0402]  71.61 92.41 0 bottom
R372  20_1%_4  [R0402]  69.38 91.55 0 bottom
R373  *S_8  [S0805]  120.36 91.2 0 bottom
R374  20_1%_4  [R0402]  71.54 91.06 0 bottom
R375  20_1%_4  [R0402]  71.54 90.05 0 bottom
R376  TPM@20_1%_4  [R0402]  61.63 89.74 0 bottom
R377  *10K_5%_4  [R0402]  108.72 89.34 180 bottom
R378  *S_8  [S0805]  120.37 89.05 0 bottom
R379  20_1%_4  [R0402]  71.54 89.03 0 bottom
R380  *DBG@20_1%_4  [R0402]  61.63 88.73 0 bottom
R381  2.2K_5%_4  [R0402]  55.99 88.32 0 bottom
R382  *0_5%_4  [R0402]  108.72 88.32 180 bottom
R383  *S_6  [S0603]  120.2 87.35 0 bottom
R384  *10K_5%_4  [R0402]  69.58 87.15 0 bottom
R385  402_1%_4  [R0402]  108.72 86.61 0 bottom
R386  20_1%_4  [R0402]  59.7 86.39 180 bottom
R387  *S_6  [S0603]  123.69 86.25 270 bottom
R388  *0_5%_6  [R0603]  125.12 86.25 270 bottom
R389  10K_5%_4  [R0402]  69.58 85.68 0 bottom
R390  10K_5%_4  [R0402]  63.49 85.6 0 bottom
R391  10K_5%_4  [R0402]  65.52 85.58 180 bottom
R392  *10K_5%_4  [R0402]  67.55 85.58 0 bottom
R393  *S_4  [S0402]  42.86 84.93 0 bottom
R394  *S_6  [S0603]  113.78 84.54 0 bottom
R395  *S_4  [S0402]  115.58 84.27 270 bottom
R396  *S_6  [S0603]  113.78 83.01 0 bottom
R397  10K_5%_4  [R0402]  59.88 75.91 270 bottom
R398  10K_5%_4  [R0402]  60.84 75.91 270 bottom
R399  33_5%_4  [R0402]  62.05 75.91 270 bottom
R400  100K_5%_4  [R0402]  16.24 73.79 270 bottom
R401  *0_5%_4  [R0402]  17.23 73.79 270 bottom
R402  *S_4  [S0402]  18.2 73.79 270 bottom
R403  *S_4  [S0402]  19.12 68.71 180 bottom
R404  *S_4  [S0402]  19.12 67.75 180 bottom
R405  *S_4  [S0402]  19.12 66.55 180 bottom
R406  *S_4  [S0402]  19.12 65.59 180 bottom
R407  *S_4  [S0402]  19.12 64.38 180 bottom
R408  *S_4  [S0402]  19.12 63.42 180 bottom
R409  *S_4  [S0402]  19.12 62.21 180 bottom
R410  *S_4  [S0402]  19.12 61.25 180 bottom
R411  240_1%_4  [R0402]  103.77 52.58 90 bottom
R412  240_1%_4  [R0402]  68.52 52.38 90 bottom
R413  240_1%_4  [R0402]  85.84 49.87 270 bottom
R414  240_1%_4  [R0402]  50.61 49.61 270 bottom
R415  3.3K_5%_4  [R0402]  145.4 41.35 270 bottom
R416  *S_4  [S0402]  205.4 40.51 0 bottom
R417  3.3K_5%_4  [R0402]  133.97 40.21 270 bottom
R418  10K_5%_4  [R0402]  165.98 36.4 180 top
R419  80.6_1%_4  [R0402]  61.2 39.07 270 bottom
R420  80.6_1%_4  [R0402]  62.22 39.07 270 bottom
R421  80.6_1%_4  [R0402]  63.23 39.07 270 bottom
R422  80.6_1%_4  [R0402]  64.25 39.07 270 bottom
R423  80.6_1%_4  [R0402]  65.26 39.07 270 bottom
R424  80.6_1%_4  [R0402]  66.28 39.07 270 bottom
R425  80.6_1%_4  [R0402]  67.3 39.07 270 bottom
R426  80.6_1%_4  [R0402]  68.31 39.07 270 bottom
R427  80.6_1%_4  [R0402]  69.33 39.07 270 bottom
R428  80.6_1%_4  [R0402]  70.34 39.07 270 bottom
R429  80.6_1%_4  [R0402]  71.36 39.07 270 bottom
R430  80.6_1%_4  [R0402]  72.38 39.07 270 bottom
R431  80.6_1%_4  [R0402]  95.36 39.07 270 bottom
R432  80.6_1%_4  [R0402]  96.38 39.07 270 bottom
R433  80.6_1%_4  [R0402]  97.4 39.07 270 bottom
R434  80.6_1%_4  [R0402]  98.41 39.07 270 bottom
R435  80.6_1%_4  [R0402]  99.43 39.07 270 bottom
R436  80.6_1%_4  [R0402]  100.44 39.07 270 bottom
R437  80.6_1%_4  [R0402]  101.46 39.07 270 bottom
R438  80.6_1%_4  [R0402]  102.48 39.07 270 bottom
R439  80.6_1%_4  [R0402]  103.49 39.07 270 bottom
R440  80.6_1%_4  [R0402]  104.51 39.07 270 bottom
R441  80.6_1%_4  [R0402]  105.52 39.07 270 bottom
R442  80.6_1%_4  [R0402]  106.54 39.07 270 bottom
R443  10K_5%_4  [R0402]  131.95 39.07 180 bottom
R444  4.7K_5%_4  [R0402]  207.86 38.92 270 bottom
R445  3.3K_5%_4  [R0402]  145.4 38.81 270 bottom
R446  100K_5%_4  [R0402]  146.67 31.58 270 bottom
R447  *4.7K_5%_4  [R0402]  207.48 37.2 270 bottom
R448  *S_4  [S0402]  150.09 37.14 180 bottom
R449  ODD@12.1K_1%_4  [R0402]  116.53 36.4 270 bottom
R450  *S_4  [S0402]  150.09 34 180 bottom
R451  4.7K_5%_4  [R0402]  206.3 33.95 270 bottom
R452  *4.7K_5%_4  [R0402]  207.28 33.48 270 bottom
R453  *4.7K_5%_4  [R0402]  207.73 32.14 180 bottom
R454  *0_5%_4  [R0402]  130.16 35.13 0 bottom
R455  *0_5%_4  [R0402]  132.19 34.37 270 bottom
R456  ODD@4.7K_5%_4  [R0402]  110.98 32.85 0 bottom
R457  *10K_5%_4  [R0402]  133.46 33.59 90 bottom
R458  ODD@4.7K_5%_4  [R0402]  110.98 31.89 0 bottom
R459  2.2_5%_6  [R0603]  148.55 30.74 90 bottom
R460  *S_4  [S0402]  203.31 28.91 270 bottom
R461  *S_8  [S0805]  144.89 28.15 180 bottom
R462  100K_5%_4  [R0402]  132.57 27.99 270 bottom
R463  1K_1%_4  [R0402]  192.28 27.67 90 bottom
R464  *DBG@0_5%_4  [R0402]  150.19 27.31 0 bottom
R465  4.7K_5%_4  [R0402]  207.38 26.65 270 bottom
R466  62_1%_4  [R0402]  208.39 26.65 90 bottom
R467  *22_5%_4  [R0402]  131.22 25.98 0 bottom
R468  EJ@68.1K_1%_4  [R0402]  189.67 25.43 180 bottom
R469  EJ@150K_1%_4  [R0402]  191.45 25.61 180 bottom
R470  ODD@4.7K_5%_4  [R0402]  119.54 25.35 270 bottom
R471  ODD@4.7K_5%_4  [R0402]  121.46 25.35 270 bottom
R472  ODD@100K_5%_4  [R0402]  117.62 24.35 90 bottom
R473  *S_4  [S0402]  203.18 24.22 90 bottom
R474  EJ@4.7K_5%_4  [R0402]  189.39 24.08 90 bottom
R475  EJ@4.7K_5%_4  [R0402]  191.43 23.97 180 bottom
R476  4.7K_5%_4  [R0402]  207.63 21.07 180 bottom
R477  2.2K_5%_4  [R0402]  201.31 20.86 270 bottom
R478  2.2K_5%_4  [R0402]  202.47 20.86 270 bottom
R479  *S_4  [S0402]  202.37 18.9 270 bottom
R480  100K_5%_4  [R0402]  130.53 15.8 0 bottom
R481  100K_5%_4  [R0402]  131.23 16.34 0 top
R483  *10K_5%_4  [R0402]  168.64 30.56 180 top
R484  *PSD@10K_5%_4  [R0402]  28.82 96.47 180 top
R485  *0_5%_4  [R0402]  58.79 75.91 270 bottom
R486  *0_5%_4  [R0402]  71.84 84.16 180 bottom
R487  *10K_5%_4  [R0402]  110.35 109.43 90 bottom
R488  10K_5%_4  [R0402]  106.79 109.43 90 bottom
R489  *10K_5%_4  [R0402]  166.48 30.05 180 top
R490  *PSD@10K_5%_4  [R0402]  28.82 97.49 0 top
R491  10K_5%_4  [R0402]  96.89 104.22 0 bottom
R492  *10K_5%_4  [R0402]  97.52 105.49 180 bottom
R493  10_5%_4  [R0402]  139.28 36.15 270 top
SPAD1  *SPAD-C315NP  [SPAD-C315NP]  137.7 74.98 0 top
SPAD2  *SPAD-C236NP  [SPAD-C236NP]  46.7 51.8 0 top
SPAD3  *SPAD-C236NP  [SPAD-C236NP]  134.2 51.8 0 top
SPAD4  *SPAD-C236NP  [SPAD-C236NP]  69.2 13.3 0 top
SPAD5  *SPAD-C177NP  [SPAD-C177NP]  235.92 32.7 90 top
SPAD6  *SPAD-C177NP  [SPAD-C177NP]  200.42 10.3 90 top
SW1  TME-532W-Q-T/R  [SW-TME-532-V-6P]  139 25.7 270 bottom
SW2  JTE1CQR  [SW-DS-A40E-4P-SMT]  126 30.1 180 bottom
SW3  *TME-532W-Q-T/R  [SW-TME-532-V-6P]  141.21 33.61 0 bottom
TP1  *TP  [TP2050]  85.38 94.42 0 top
TP2  *TP  [TP2050]  85.36 93.15 0 top
TP3  *TP  [TP2050]  9.79 90.82 0 top
TP4  *TP  [TP2050]  11.09 90.69 0 top
TP5  *TP  [TP2050]  79.56 90.96 0 top
TP6  *TP  [TP2050]  73.26 84.82 0 top
TP7  *TP  [TP2050]  82.91 84.48 0 top
TP8  *TP  [TP2050]  76.55 83.04 0 top
TP9  *TP  [TP2050]  80.41 83.04 0 top
TP10  *TP  [TP2050]  77.9 83 0 top
TP11  *TP  [TP2050]  30.64 43.34 90 top
TP12  *TP  [TP2050]  32.19 41.61 270 top
TP13  *TP  [TP2050]  30.85 41.48 270 top
TP14  *TP  [TP2050]  31.91 40.34 270 top
TP15  *TP  [TP2050]  136.88 35.6 0 top
TP16  *TP  [TP2050]  153.25 34.96 90 top
TP17  *TP  [TP2050]  133.82 34.07 0 top
TP18  *TP  [TP2050]  146.56 32.22 0 top
TP19  *TP  [TP2050]  197.78 30.23 0 top
TP20  *TP  [TP2050]  129.2 29.05 0 top
TP21  *TP  [TP2050]  150.41 27.76 0 top
TP22  *TP  [TP2050]  149.14 27.13 0 top
TP23  *TP  [TP2050]  149.59 25.44 0 top
TP24  *TP  [TP2050]  128.76 24.1 0 top
TP25  *TP  [TP2050]  129.74 23.24 0 top
TP26  *TP  [TP2050]  148.75 21.37 0 top
TP27  *TP  [TP2050]  149.81 20.67 0 top
TP28  *TP  [TP2050]  131.79 15.27 0 top
TP29  *TP  [TP2050]  119.12 131.58 90 bottom
TP30  *TP  [TP2050]  115.37 119.5 90 bottom
TP32  *TP  [TP2050]  96.46 101.86 180 bottom
TP33  *TP  [TP2050]  26.58 87.69 180 bottom
TP34  *TP  [TP2050]  27.9 87.36 180 bottom
TP35  *TP  [TP2050]  38.12 87.41 180 bottom
TP36  *TP  [TP2050]  71.59 86.26 180 bottom
TP37  *TP  [TP2050]  72.2 85.1 180 bottom
TP38  *TP  [TP2050]  70.9 85.08 180 bottom
TP39  *TP  [TP2050]  120.72 75.71 90 bottom
TP40  *TP  [TP2050]  28.14 38.59 270 bottom
TP41  *TP  [TP2050]  116.14 26.11 0 bottom
TP42  *TP  [TP2050]  116.14 24.84 0 bottom
TP43  *TP  [TP2050]  130.06 15.5 0 top
U1  GD25LB64CSIGR  [SOIC8-7_9-1_27-2_16H]  69.99 123.65 180 top
U2  EC@Hynix 32GB  [FBGA169-SAMSUNG-KMHOG0000M-0_5S]  57.64 97.24 90 top
U3  TPC@TPS25810RVCR  [QFN20-4X3-5-21P]  27.8 89.11 90 top
U4  PSD@NTS0101GW  [SC70-2_1-65-6P]  33.01 96.47 90 top
U5  G5250Q1T73U  [SOT23_213-3_3-2]  23.78 75.7 270 top
U6  *PTN3366BS  [QFN32-5X5-5-37P-0_85H]  29.7 65.23 180 top
U7  G524B2T11U  [SOT23-5]  25.01 55.84 270 top
U8  H5TC4G63EFR-PBA  [BGA96-ELPIDA-EDJ4216EBBG-DJ-F]  57.77 52.28 0 top
U9  H5TC4G63EFR-PBA  [BGA96-ELPIDA-EDJ4216EBBG-DJ-F]  75.68 52.28 0 top
U10  H5TC4G63EFR-PBA  [BGA96-ELPIDA-EDJ4216EBBG-DJ-F]  92.95 52.28 0 top
U11  H5TC4G63EFR-PBA  [BGA96-ELPIDA-EDJ4216EBBG-DJ-F]  110.86 52.28 0 top
U12  SN75LVCP601RTJR  [PWQFN20-4X4-5-26P-0_8H]  205.47 37.8 270 top
U13  RTL8411B-CG  [QFN48-6X6-4-49P-ALC280]  28.18 35.51 270 top
U14  TPM@NPCT650ABBYX  [QFN32-5X5-5-33P-0_85H]  157.97 34.37 270 top
U15  ALC255-CG  [QFN48-6X6-4-49P-ALC280]  201.89 26.6 270 top
U16  IT8987E/CX  [LQFP128-16X16-4-1_6H]  139.28 24.26 270 top
U17  GS@LIS3DHTR  [LGA16-3X3-5]  156.68 15.17 90 top
U18  G524B2T11U  [SOT23-5]  224.51 14.09 180 top
U19  G5245AT11U  [SOT23-5-2_8-95-5P-G708]  64.76 106.38 90 bottom
U20  NS892407  [TRF-15_1X10-1-25P]  31.2 104.96 180 bottom
U21  APL_BGA_1296P  [BGA1296-INTEL-APOLLO-LAKE]  90.2 86.8 270 bottom
U22  NTS0101GW  [SC70-2_1-65-6P]  60.43 84.6 180 bottom
U23  CB@G753T11U  [SOT23-5-2_8-95-5P-G708]  117.33 76.66 0 bottom
U24  H5TC4G63EFR-PBA  [BGA96-ELPIDA-EDJ4216EBBG-DJ-F]  57.77 52.28 180 bottom
U25  H5TC4G63EFR-PBA  [BGA96-ELPIDA-EDJ4216EBBG-DJ-F]  75.68 52.28 180 bottom
U26  H5TC4G63EFR-PBA  [BGA96-ELPIDA-EDJ4216EBBG-DJ-F]  92.95 52.28 180 bottom
U27  H5TC4G63EFR-PBA  [BGA96-ELPIDA-EDJ4216EBBG-DJ-F]  110.86 52.28 180 bottom
U28  W25Q80BWSSIG  [SOIC8-7_9-1_27-2_16H]  139.69 39.83 270 bottom
U29  NTS0101GW  [SC70-2_1-65-6P]  167.63 34.63 180 top
U30  G9090-180T11U  [TSOT23-2_8-95-5P-G916-475TOUF]  147.56 35.26 270 bottom
U31  ODD@W25X10CLSNIG  [SOIC8-6-1_27]  105.9 34.81 270 bottom
U32  ODD@ASM1153  [QFN48-6X6-4-49P-ASM1153]  116.45 30.94 90 bottom
Y1  32.768KHZ/20ppm  [XTL-3_2X1_5-2_5-0_8H]  66.53 90.05 90 top
Y2  25MHZ/30ppm  [XTL-3_2X2_5-2_2X1_7-4P-1H]  27.84 42.78 180 top
Y3  19.2MHZ/20ppm  [XTL-3_2X2_5-2_2X1_7-0_8H]  100.06 108.67 180 bottom
Y4  ODD@25MHZ/30ppm  [XTL-3_2X2_5-2_2X1_7-4P-1H]  122.03 37.42 0 bottom

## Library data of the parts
C1 C2 C4-C17 C19-C21 C23-C449 PC1-PC19 PC21-PC79 PC81-PC164 PC166-PC214 PC216 = CAP NON-POL_BGM
C3 PC20 PC80 PC165 = CAP POL_BGM
CN1 = USB3_1_24P_6fix_BGM
CN2 = SDCARD_156-1001902602_BGM
CN3 = FFCFPC_40P_BGM
CN4 = RJ45_8P_4F_BGM
CN5 = NGFF_79P_MKEY_FT_BGM
CN6 = HDMI_19P_BGM
CN7 = Header_2P_BGM
CN8 = USB3_13P_BGM
CN9 = NGFF_79P_EKEY_FT_BGM
CN10 CN19 = Header_4P_BGM
CN11 = FFCFPC_10P_BGM
CN12 = Housing_20P_FIX6P_BGM
CN13 = RTC_4P_BGM
CN14 = FFCFPC_28P_BGM
CN15 = FFCFPC_8P_BGM
CN16 = FFCFPC_18P_BGM
CN17 = FFCFPC_34P_BGM
CN18 = FFCFPC_4P_BGM
D1 D23 D25 PD4 = DIODE_BGM
D2 D7 D8 D15-D22 D24 PD1 PD7 = Schottky_DIODE_BGM
D3 = TVS_DIODE_BGM_0
D4 D5 D9-D14 D27 D28 = TVS_DIODE_BGM
D6 D29 D30 = Varistor_BGM
D26 = BAT54C_BGM
ESD1 ESD4 ESD5 = TVL ST23 04 AD0_BGM
ESD2 = AZ1043-08F.R7G_BGM
ESD3 = AZ1065-06F.R7G_10P-BGM
ESD6 ESD7 = AZ1045-04F_BGM
HOLE1 HOLE3 HOLE4 HOLE6 HOLE7 HOLE9 HOLE10 SPAD1-SPAD6 = 3x2_1.1
HOLE2 HOLE5 HOLE8 HOLE11-HOLE15 = 3x2_0.1
J1 = OPEN
JP1-JP12 PR44 PR78 = R_Current_SEN_BGM
L1-L3 L6 L7 = BW_BGM
L4 L5 L8 L9 L11 L12 = BEAD_BGM
L10 PL1-PL10 = INDUCTOR_BGM
PD2 PD5 PD6 = ZENER_DIODE_BGM
PD3 = SV1040_3P_BGM
PJ1 = Single_4P_NOFIX_BGM
PJ2 = Housing_6P_BGM
PJ5 = Header_8P_BGM
PQ1 PQ3 PQ5 PQ7 PQ8 PQ10 PQ15 PQ23 PQ25 Q1 Q5 Q6 Q8 Q9 Q12 Q13 Q17 Q30-Q32 = MOS-N_3P_ESD_BGM
PQ2 PQ24 Q2 Q23 = DTC144EU_BGM
PQ4 = MOS-N_3P_BGM
PQ6 PQ17 Q7 = MOS-P_8P_BGM
PQ9 Q3 Q4 Q10 Q11 Q15 Q19-Q21 Q24-Q29 Q33 Q35 Q36 = MOS-N_Dual_6P_ESD_BGM
PQ11 PQ13 PQ18 PQ20 PQ21 = MOS-N_8P_BGM
PQ12 PQ14 PQ19 = MOS-N_8P_SCH_BGM
PQ16 = IMD2AT108_BGM
PQ22 = MOS-P_3P_ESD_BGM
PR1-PR33 PR35-PR43 PR45-PR77 PR79-PR109 PR111 PR112 PR114 PR115 PR117-PR133 PR136-PR138 PR141-PR174 PR179-PR212 R1-R45 R47-R52 R54-R88 R90-R123 R125 R126 R129 R130 R132-R135 R137-R140 R142-R481 R483-R493 = RES_BGM
PR110 PR113 PR116 = Thermistor_BGM
PU1 = TPS61087DRCR_BGM
PU2 = BQ24737RGRR_BGM
PU3 PU4 = ISL95808HRZ-T_BGM
PU5 = SY8286BRAC_BGM
PU6 = ISL95859HRTZ-T_BGM
PU7 PU13 = AOZ1331DI_BGM
PU8 = M5671RE1U_BGM
PU9 = TMP708_BGM
PU10 PU12 = G5719CTB1U_BGM
PU11 = SY8288CRAC_BGM
PU14 = G9661-25ADJF12U_BGM
PU15 = RT8231BGQW_BGM
Q14 = HALL_IC_3P_BGM
Q16 Q34 = NPN_BGM
Q22 = MOS-P_3P_BGM
R89 = RES_BGM_0
SW1-SW3 = SW_6P_BGM
TP1-TP30 TP32-TP43 = TP_BGM
U1 = SPI_GD25LB64CSIGR_BGM
U2 = EMMC_169P_BGM
U3 = TPS25810RVCR_BGM
U4 U22 U29 = NTS0101GW_BGM
U5 = G5250Q1T73U_BGM
U6 = PTN3366BS_BGM
U7 U18 = G524B2T11U_BGM
U8-U11 U24-U27 = DDR3L_96P_MT41K256M16TW-107_BGM
U12 = SN75LVCP601RTJR_BGM
U13 = RTL8411B-CG_BGM
U14 = NPCT650ABAYX_BGM
U15 = ALC255-CG_BGM
U16 = IT8987E/CX_BGM
U17 = LIS3DHTR_BGM
U19 = G5245AT11U_BGM
U20 = A-1010G_BGM
U21 = CPU_APL_SOC_DDR3_BGM
U23 = G753T11U_BGM
U28 = SPI_W25Q80EWSSIG_BGM
U30 = G9090-180T11U_BGM
U31 = W25X10CLSNIG_BGM
U32 = ASM1153_BGM
Y1 = CRYSTAL_2P_BGM
Y2-Y4 = CRYSTAL_4P_BGM

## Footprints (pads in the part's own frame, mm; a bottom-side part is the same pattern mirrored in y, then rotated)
132F10-000000-A2-R-10P-L
  rect 0.305x0.838 smd: 1(-2.25,3.175) 2(-1.75,3.175) 3(-1.25,3.175) 4(-0.75,3.175) 5(-0.25,3.175) 6(0.25,3.175) 7(0.75,3.175) 8(1.25,3.175) 9(1.75,3.175) 10(2.25,3.175)
  rect 0.787x2.007 smd: 11(-3.95,0) 12(3.95,0)
50278-006T1-001-6P-L
  rect 0.787x1.905 smd: 1(-3.125,4.925) 2(-1.875,4.925) 3(-0.625,4.925) 4(0.625,4.925) 5(1.875,4.925) 6(3.125,4.925)
  rect 1.295x3.353 smd: 7(-5.975,0) 8(5.975,0)
50278-00401-001-4P-L
  rect 0.787x1.905 smd: 1(-1.875,4.925) 2(-0.625,4.925) 3(0.625,4.925) 4(1.875,4.925)
  rect 1.295x3.353 smd: 5(-4.725,0) 6(4.725,0)
50281-00201-001-2P-L
  rect 0.787x2.007 smd: 1(-0.625,4.05) 2(0.625,4.05)
  rect 2.007x2.489 smd: 3(-2.825,0) 4(2.825,0)
50320-0040N-001-4P-L-SMT
  round 1.422 hole 1.016: 1(-3.75,2.9) 2(-1.25,2.9) 3(1.25,2.9) 4(3.75,2.9)
50458-00801-V02-8P-L
  rect 0.559x1.295 smd: 1(-7,5.025) 2(-5,5.025) 3(-3,5.025) 4(-1,5.025) 5(1,5.025) 6(3,5.025) 7(5,5.025) 8(7,5.025)
  rect 1.295x2.057 smd: 9(-10.1,0) 10(10.1,0)
50584-0280N-V02-28P-L
  rect 0.61x1.092 smd: 1(-13.5,2.05) 2(-12.5,2.05) 3(-11.5,2.05) 4(-10.5,2.05) 5(-9.5,2.05) 6(-8.5,2.05) 7(-7.5,2.05) 8(-6.5,2.05) 9(-5.5,2.05) 10(-4.5,2.05) 11(-3.5,2.05) 12(-2.5,2.05) 13(-1.5,2.05) 14(-0.5,2.05) 15(0.5,2.05) 16(1.5,2.05) 17(2.5,2.05) 18(3.5,2.05) 19(4.5,2.05) 20(5.5,2.05) 21(6.5,2.05) 22(7.5,2.05) 23(8.5,2.05) 24(9.5,2.05) 25(10.5,2.05) 26(11.5,2.05) 27(12.5,2.05) 28(13.5,2.05)
  rect 2.159x2.997 smd: 29(-15.975,0) 30(15.975,0)
50591-00401-001-4P-L
  rect 0.61x1.092 smd: 1(-1.5,2.15) 2(-0.5,2.15) 3(0.5,2.15) 4(1.5,2.15)
  rect 2.21x3.2 smd: 5(-4,0) 6(4,0)
51540-04001-V01-40P-L
  rect 0.305x0.838 smd: 1(-9.75,3.175) 2(-9.25,3.175) 3(-8.75,3.175) 4(-8.25,3.175) 5(-7.75,3.175) 6(-7.25,3.175) 7(-6.75,3.175) 8(-6.25,3.175) 9(-5.75,3.175) 10(-5.25,3.175) 11(-4.75,3.175) 12(-4.25,3.175) 13(-3.75,3.175) 14(-3.25,3.175) 15(-2.75,3.175) 16(-2.25,3.175) 17(-1.75,3.175) 18(-1.25,3.175) 19(-0.75,3.175) 20(-0.25,3.175) 21(0.25,3.175) 22(0.75,3.175) 23(1.25,3.175) 24(1.75,3.175) 25(2.25,3.175) 26(2.75,3.175) 27(3.25,3.175) 28(3.75,3.175) 29(4.25,3.175) 30(4.75,3.175) 31(5.25,3.175) 32(5.75,3.175) 33(6.25,3.175) 34(6.75,3.175) 35(7.25,3.175) 36(7.75,3.175) 37(8.25,3.175) 38(8.75,3.175) 39(9.25,3.175) 40(9.75,3.175)
  rect 0.787x2.007 smd: 41(-11.45,0) 42(11.45,0)
51605-01801-001-18P-L
  rect 0.305x0.838 smd: 1(-4.25,3.175) 2(-3.75,3.175) 3(-3.25,3.175) 4(-2.75,3.175) 5(-2.25,3.175) 6(-1.75,3.175) 7(-1.25,3.175) 8(-0.75,3.175) 9(-0.25,3.175) 10(0.25,3.175) 11(0.75,3.175) 12(1.25,3.175) 13(1.75,3.175) 14(2.25,3.175) 15(2.75,3.175) 16(3.25,3.175) 17(3.75,3.175) 18(4.25,3.175)
  rect 0.787x2.007 smd: 19(-5.95,0) 20(5.95,0)
51653-0080N-V02-8P-L
  rect 0.305x1.295 smd: 1(-3.5,2.65) 2(-2.5,2.65) 3(-1.5,2.65) 4(-0.5,2.65) 5(0.5,2.65) 6(1.5,2.65) 7(2.5,2.65) 8(3.5,2.65)
  rect 1.803x1.397 smd: 9(-5.65,0) 10(5.65,0)
196332-34041-3-34P-L
  rect 0.305x1.295 smd: 1(-8.25,2.8) 2(-7.75,2.8) 3(-7.25,2.8) 4(-6.75,2.8) 5(-6.25,2.8) 6(-5.75,2.8) 7(-5.25,2.8) 8(-4.75,2.8) 9(-4.25,2.8) 10(-3.75,2.8) 11(-3.25,2.8) 12(-2.75,2.8) 13(-2.25,2.8) 14(-1.75,2.8) 15(-1.25,2.8) 16(-0.75,2.8) 17(-0.25,2.8) 18(0.25,2.8) 19(0.75,2.8) 20(1.25,2.8) 21(1.75,2.8) 22(2.25,2.8) 23(2.75,2.8) 24(3.25,2.8) 25(3.75,2.8) 26(4.25,2.8) 27(4.75,2.8) 28(5.25,2.8) 29(5.75,2.8) 30(6.25,2.8) 31(6.75,2.8) 32(7.25,2.8) 33(7.75,2.8) 34(8.25,2.8)
  rect 1.803x1.397 smd: 35(-9.9,0) 36(9.9,0)
BGA96-ELPIDA-EDJ4216EBBG-DJ-F
  round 0.356 smd: A1(-3.2,6) A2(-2.4,6) A3(-1.6,6) A7(1.6,6) A8(2.4,6) A9(3.2,6) B1(-3.2,5.2) B2(-2.4,5.2) B3(-1.6,5.2) B7(1.6,5.2) B8(2.4,5.2) B9(3.2,5.2) C1(-3.2,4.4) C2(-2.4,4.4) C3(-1.6,4.4) C7(1.6,4.4) C8(2.4,4.4) C9(3.2,4.4) D1(-3.2,3.6) D2(-2.4,3.6) D3(-1.6,3.6) D7(1.6,3.6) D8(2.4,3.6) D9(3.2,3.6) E1(-3.2,2.8) E2(-2.4,2.8) E3(-1.6,2.8) E7(1.6,2.8) E8(2.4,2.8) E9(3.2,2.8) F1(-3.2,2) F2(-2.4,2) F3(-1.6,2) F7(1.6,2) F8(2.4,2) F9(3.2,2) G1(-3.2,1.2) G2(-2.4,1.2) G3(-1.6,1.2) G7(1.6,1.2) G8(2.4,1.2) G9(3.2,1.2) H1(-3.2,0.4) H2(-2.4,0.4) H3(-1.6,0.4) H7(1.6,0.4) H8(2.4,0.4) H9(3.2,0.4) J1(-3.2,-0.4) J2(-2.4,-0.4) J3(-1.6,-0.4) J7(1.6,-0.4) J8(2.4,-0.4) J9(3.2,-0.4) K1(-3.2,-1.2) K2(-2.4,-1.2) K3(-1.6,-1.2) K7(1.6,-1.2) K8(2.4,-1.2) K9(3.2,-1.2) L1(-3.2,-2) L2(-2.4,-2) L3(-1.6,-2) L7(1.6,-2) L8(2.4,-2) L9(3.2,-2) M1(-3.2,-2.8) M2(-2.4,-2.8) M3(-1.6,-2.8) M7(1.6,-2.8) M8(2.4,-2.8) M9(3.2,-2.8) N1(-3.2,-3.6) N2(-2.4,-3.6) N3(-1.6,-3.6) N7(1.6,-3.6) N8(2.4,-3.6) N9(3.2,-3.6) P1(-3.2,-4.4) P2(-2.4,-4.4) P3(-1.6,-4.4) P7(1.6,-4.4) P8(2.4,-4.4) P9(3.2,-4.4) R1(-3.2,-5.2) R2(-2.4,-5.2) R3(-1.6,-5.2) R7(1.6,-5.2) R8(2.4,-5.2) R9(3.2,-5.2) T1(-3.2,-6) T2(-2.4,-6) T3(-1.6,-6) T7(1.6,-6) T8(2.4,-6) T9(3.2,-6)
BGA1296-INTEL-APOLLO-LAKE
  round 0.47 smd: A3(-11.314,-13.954) A62(-11.314,14.382) B2(-10.883,-14.383) B63(-10.883,14.814) BH1(10.883,-14.814) BH63(10.883,14.814) BJ2(11.314,-14.382) BJ62(11.314,14.382) C1(-10.454,-14.814)
  round 0.356 smd: A4(-11.314,-13.221) A5(-11.314,-12.548) A7(-11.314,-11.697) A9(-11.314,-11.024) A56(-11.314,11.411) A58(-11.314,12.439) A60(-11.314,13.112) A61(-11.314,13.786) B3(-10.72,-13.759) B4(-10.72,-13.162) B5(-10.72,-12.565) B8(-10.72,-11.371) B57(-10.72,11.841) B58(-10.72,12.438) B60(-10.72,13.035) B61(-10.72,13.632) B62(-10.738,14.238) BB1(8.089,-14.814) BB63(8.089,14.814) BC2(8.354,-14.22) BC62(8.354,14.22) BD1(8.94,-14.814) BD2(8.95,-14.22) BD62(8.95,14.22) BD63(8.94,14.814) BE1(9.613,-14.814) BE2(9.547,-14.22) BE62(9.547,14.22) BE63(9.613,14.814) BG1(10.286,-14.814) BG2(10.144,-14.22) BG62(10.144,14.22) BG63(10.286,14.814) BH2(10.738,-14.238) BH3(10.72,-13.632) BH4(10.72,-13.035) BH6(10.72,-12.438) BH7(10.72,-11.841) BH57(10.72,11.841) BH58(10.72,12.438) BH60(10.72,13.035) BH61(10.72,13.632) BH62(10.738,14.238) BJ3(11.314,-13.786) BJ4(11.314,-13.112) BJ6(11.314,-12.439) BJ8(11.314,-11.411) BJ56(11.314,11.411) BJ58(11.314,12.439) BJ60(11.314,13.112) BJ61(11.314,13.786) C2(-10.259,-14.22) C62(-10.144,14.22) C63(-10.286,14.814) D1(-9.724,-14.814) D2(-9.665,-14.22) E62(-9.547,14.22) E63(-9.613,14.814) F1(-9.051,-14.814) F2(-9.072,-14.22) F62(-8.95,14.22) F63(-8.94,14.814) G1(-8.2,-14.814) G2(-8.474,-14.258) G62(-8.354,14.22) H63(-8.089,14.814) J1(-7.527,-14.814)
  custom 0.064x0.064 smd: A10(-11.314,-10.198) A12(-11.314,-9.271) A14(-11.314,-8.344) A16(-11.314,-7.417) A18(-11.314,-6.49) A20(-11.314,-5.563) A22(-11.314,-4.636) A24(-11.314,-3.708) A26(-11.314,-2.781) A28(-11.314,-1.854) A30(-11.314,-0.927) A32(-11.314,0) A34(-11.314,0.927) A36(-11.314,1.854) A38(-11.314,2.781) A40(-11.314,3.708) A42(-11.314,4.636) A44(-11.314,5.563) A46(-11.314,6.49) A48(-11.314,7.417) A50(-11.314,8.344) A52(-11.314,9.271) A54(-11.314,10.198) AA1(-1.854,-14.814) AA63(-1.854,14.814) AC1(-0.927,-14.814) AC63(-0.927,14.814) AE1(0,-14.814) AE63(0,14.814) AG1(0.927,-14.814) AG63(0.927,14.814) AJ1(1.854,-14.814) AJ63(1.854,14.814) AL1(2.781,-14.814) AL63(2.781,14.814) AN1(3.708,-14.814) AN63(3.708,14.814) AR1(4.636,-14.814) AR63(4.636,14.814) AU1(5.563,-14.814) AU63(5.563,14.814) AW1(6.49,-14.814) AW63(6.49,14.814) BA1(7.417,-14.814) BA63(7.417,14.814) BJ10(11.314,-10.198) BJ12(11.314,-9.271) BJ14(11.314,-8.344) BJ16(11.314,-7.417) BJ18(11.314,-6.49) BJ20(11.314,-5.563) BJ22(11.314,-4.636) BJ24(11.314,-3.708) BJ26(11.314,-2.781) BJ28(11.314,-1.854) BJ30(11.314,-0.927) BJ32(11.314,0) BJ34(11.314,0.927) BJ36(11.314,1.854) BJ38(11.314,2.781) BJ40(11.314,3.708) BJ42(11.314,4.636) BJ44(11.314,5.563) BJ46(11.314,6.49) BJ48(11.314,7.417) BJ50(11.314,8.344) BJ52(11.314,9.271) BJ54(11.314,10.198) J63(-7.417,14.814) L1(-6.49,-14.814) L63(-6.49,14.814) N1(-5.563,-14.814) N63(-5.563,14.814) R1(-4.636,-14.814) R63(-4.636,14.814) U1(-3.708,-14.814) U63(-3.708,14.814) W1(-2.781,-14.814) W63(-2.781,14.814)
  round 0.279 smd: AA2(-1.854,-14.037) AA62(-1.854,14.037) AB2(-1.391,-14.414) AB3(-1.391,-13.66) AB61(-1.391,13.66) AB62(-1.391,14.414) AC2(-0.927,-14.037) AC62(-0.927,14.037) AD2(-0.464,-14.414) AD3(-0.464,-13.66) AD61(-0.464,13.66) AD62(-0.464,14.414) AE2(0,-14.037) AE4(0,-13.285) AE60(0,13.285) AE62(0,14.037) AF2(0.464,-14.414) AF3(0.464,-13.66) AF61(0.464,13.66) AF62(0.464,14.414) AG2(0.927,-14.037) AG62(0.927,14.037) AH2(1.391,-14.414) AH3(1.391,-13.66) AH61(1.391,13.66) AH62(1.391,14.414) AJ2(1.854,-14.037) AJ62(1.854,14.037) AK2(2.318,-14.414) AK3(2.318,-13.66) AK61(2.318,13.66) AK62(2.318,14.414) AL2(2.781,-14.037) AL62(2.781,14.037) AM2(3.245,-14.414) AM3(3.245,-13.66) AM61(3.245,13.66) AM62(3.245,14.414) AN2(3.708,-14.037) AN62(3.708,14.037) AP2(4.172,-14.414) AP3(4.172,-13.66) AP61(4.172,13.66) AP62(4.172,14.414) AR2(4.636,-14.037) AR62(4.636,14.037) AT2(5.099,-14.414) AT3(5.099,-13.66) AT61(5.099,13.66) AT62(5.099,14.414) AU2(5.563,-14.037) AU62(5.563,14.037) AV2(6.026,-14.414) AV3(6.026,-13.66) AV61(6.026,13.66) AV62(6.026,14.414) AW2(6.49,-14.037) AW62(6.49,14.037) AY2(6.953,-14.414) AY3(6.953,-13.66) AY61(6.953,13.66) AY62(6.953,14.414) B9(-10.745,-10.774) B11(-10.914,-9.735) B13(-10.914,-8.807) B15(-10.914,-7.88) B17(-10.914,-6.953) B19(-10.914,-6.026) B21(-10.914,-5.099) B23(-10.914,-4.172) B25(-10.914,-3.245) B27(-10.914,-2.318) B29(-10.914,-1.391) B31(-10.914,-0.464) B33(-10.914,0.464) B35(-10.914,1.391) B37(-10.914,2.318) B39(-10.914,3.245) B41(-10.914,4.172) B43(-10.914,5.099) B45(-10.914,6.026) B47(-10.914,6.953) B49(-10.914,7.88) B51(-10.914,8.807) B53(-10.914,9.735) B55(-10.914,10.662) BA2(7.544,-14.22) BA62(7.544,14.22) BF32(9.78,0) BG7(10.159,-11.589) BG8(10.537,-11.125) BG9(10.159,-10.662) BG10(10.537,-10.198) BG11(10.159,-9.735) BG12(10.537,-9.271) BG13(10.159,-8.807) BG14(10.537,-8.344) BG15(10.159,-7.88) BG16(10.537,-7.417) BG17(10.159,-6.953) BG18(10.537,-6.49) BG19(10.159,-6.026) BG20(10.537,-5.563) BG21(10.159,-5.099) BG22(10.537,-4.636) BG23(10.159,-4.172) BG24(10.537,-3.708) BG25(10.159,-3.245) BG26(10.537,-2.781) BG27(10.159,-2.318) BG28(10.537,-1.854) BG29(10.159,-1.391) BG30(10.537,-0.927) BG31(10.159,-0.464) BG32(10.537,0) BG33(10.159,0.464) BG34(10.537,0.927) BG35(10.159,1.391) BG36(10.537,1.854) BG37(10.159,2.318) BG38(10.537,2.781) BG39(10.159,3.245) BG40(10.537,3.708) BG41(10.159,4.172) BG42(10.537,4.636) BG43(10.159,5.099) BG44(10.537,5.563) BG45(10.159,6.026) BG46(10.537,6.49) BG47(10.159,6.953) BG48(10.537,7.417) BG49(10.159,7.88) BG50(10.537,8.344) BG51(10.159,8.807) BG52(10.537,9.271) BG53(10.159,9.735) BG54(10.537,10.198) BG55(10.159,10.662) BG56(10.537,11.125) BG57(10.159,11.589) BH9(10.914,-10.662) BH11(10.914,-9.735) BH13(10.914,-8.807) BH15(10.914,-7.88) BH17(10.914,-6.953) BH19(10.914,-6.026) BH21(10.914,-5.099) BH23(10.914,-4.172) BH25(10.914,-3.245) BH27(10.914,-2.318) BH29(10.914,-1.391) BH31(10.914,-0.464) BH33(10.914,0.464) BH35(10.914,1.391) BH37(10.914,2.318) BH39(10.914,3.245) BH41(10.914,4.172) BH43(10.914,5.099) BH45(10.914,6.026) BH47(10.914,6.953) BH49(10.914,7.88) BH51(10.914,8.807) BH53(10.914,9.735) BH55(10.914,10.662) C9(-10.159,-10.662) C10(-10.537,-10.198) C11(-10.159,-9.735) C12(-10.537,-9.271) C13(-10.159,-8.807) C14(-10.537,-8.344) C15(-10.159,-7.88) C16(-10.537,-7.417) C17(-10.159,-6.953) C18(-10.537,-6.49) C19(-10.159,-6.026) C20(-10.537,-5.563) C21(-10.159,-5.099) C22(-10.537,-4.636) C23(-10.159,-4.172) C24(-10.537,-3.708) C25(-10.159,-3.245) C26(-10.537,-2.781) C27(-10.159,-2.318) C28(-10.537,-1.854) C29(-10.159,-1.391) C30(-10.537,-0.927) C31(-10.159,-0.464) C32(-10.537,0) C33(-10.159,0.464) C34(-10.537,0.927) C35(-10.159,1.391) C36(-10.537,1.854) C37(-10.159,2.318) C38(-10.537,2.781) C39(-10.159,3.245) C40(-10.537,3.708) C41(-10.159,4.172) C42(-10.537,4.636) C43(-10.159,5.099) C44(-10.537,5.563) C45(-10.159,6.026) C46(-10.537,6.49) C47(-10.159,6.953) C48(-10.537,7.417) C49(-10.159,7.88) C50(-10.537,8.344) C51(-10.159,8.807) C52(-10.537,9.271) C53(-10.159,9.735) C54(-10.537,10.198) C55(-10.159,10.662) C56(-10.537,11.125) C57(-10.159,11.589) D32(-9.78,0) H61(-8.001,13.66) J2(-7.417,-14.037) J62(-7.544,14.22) K2(-6.953,-14.414) K3(-6.953,-13.66) K61(-6.953,13.66) K62(-6.953,14.414) L2(-6.49,-14.037) L62(-6.49,14.037) M2(-6.026,-14.414) M3(-6.026,-13.66) M61(-6.026,13.66) M62(-6.026,14.414) N2(-5.563,-14.037) N62(-5.563,14.037) P2(-5.099,-14.414) P3(-5.099,-13.66) P61(-5.099,13.66) P62(-5.099,14.414) R2(-4.636,-14.037) R62(-4.636,14.037) T2(-4.172,-14.414) T3(-4.172,-13.66) T61(-4.172,13.66) T62(-4.172,14.414) U2(-3.708,-14.037) U62(-3.708,14.037) V2(-3.245,-14.414) V3(-3.245,-13.66) V61(-3.245,13.66) V62(-3.245,14.414) W2(-2.781,-14.037) W62(-2.781,14.037) Y2(-2.318,-14.414) Y3(-2.318,-13.66) Y61(-2.318,13.66) Y62(-2.318,14.414)
  round 0.33 smd: AA18(-1.448,-6.299) AA20(-1.448,-5.512) AA22(-1.448,-4.724) AA23(-1.448,-3.937) AA25(-1.448,-3.15) AA27(-1.448,-2.362) AA28(-1.448,-1.575) AA30(-1.448,-0.787) AA32(-1.448,0) AA34(-1.448,0.787) AA36(-1.448,1.575) AA37(-1.448,2.362) AA39(-1.448,3.15) AA41(-1.448,3.937) AA42(-1.448,4.724) AA44(-1.448,5.512) AA46(-1.448,6.299) AC18(-0.724,-6.299) AC20(-0.724,-5.512) AC22(-0.724,-4.724) AC23(-0.724,-3.937) AC25(-0.724,-3.15) AC27(-0.724,-2.362) AC28(-0.724,-1.575) AC30(-0.724,-0.787) AC32(-0.724,0) AC34(-0.724,0.787) AC36(-0.724,1.575) AC37(-0.724,2.362) AC39(-0.724,3.15) AC41(-0.724,3.937) AC42(-0.724,4.724) AC44(-0.724,5.512) AC46(-0.724,6.299) AE18(0,-6.299) AE20(0,-5.512) AE22(0,-4.724) AE23(0,-3.937) AE25(0,-3.15) AE27(0,-2.362) AE28(0,-1.575) AE30(0,-0.787) AE32(0,0) AE34(0,0.787) AE36(0,1.575) AE37(0,2.362) AE39(0,3.15) AE41(0,3.937) AE42(0,4.724) AE44(0,5.512) AE46(0,6.299) AG18(0.724,-6.299) AG20(0.724,-5.512) AG22(0.724,-4.724) AG23(0.724,-3.937) AG25(0.724,-3.15) AG27(0.724,-2.362) AG28(0.724,-1.575) AG30(0.724,-0.787) AG32(0.724,0) AG34(0.724,0.787) AG36(0.724,1.575) AG37(0.724,2.362) AG39(0.724,3.15) AG41(0.724,3.937) AG42(0.724,4.724) AG44(0.724,5.512) AG46(0.724,6.299) AJ18(1.448,-6.299) AJ20(1.448,-5.512) AJ22(1.448,-4.724) AJ23(1.448,-3.937) AJ25(1.448,-3.15) AJ27(1.448,-2.362) AJ28(1.448,-1.575) AJ30(1.448,-0.787) AJ32(1.448,0) AJ34(1.448,0.787) AJ36(1.448,1.575) AJ37(1.448,2.362) AJ39(1.448,3.15) AJ41(1.448,3.937) AJ42(1.448,4.724) AJ44(1.448,5.512) AJ46(1.448,6.299) AK18(2.172,-6.299) AK20(2.172,-5.512) AK22(2.172,-4.724) AK23(2.172,-3.937) AK25(2.172,-3.15) AK27(2.172,-2.362) AK28(2.172,-1.575) AK30(2.172,-0.787) AK32(2.172,0) AK34(2.172,0.787) AK36(2.172,1.575) AK37(2.172,2.362) AK39(2.172,3.15) AK41(2.172,3.937) AK42(2.172,4.724) AK44(2.172,5.512) AK46(2.172,6.299) AM18(2.896,-6.299) AM20(2.896,-5.512) AM22(2.896,-4.724) AM23(2.896,-3.937) AM25(2.896,-3.15) AM27(2.896,-2.362) AM28(2.896,-1.575) AM30(2.896,-0.787) AM32(2.896,0) AM34(2.896,0.787) AM36(2.896,1.575) AM37(2.896,2.362) AM39(2.896,3.15) AM41(2.896,3.937) AM42(2.896,4.724) AM44(2.896,5.512) AM46(2.896,6.299) AN18(3.619,-6.299) AN20(3.619,-5.512) AN22(3.619,-4.724) AN23(3.619,-3.937) AN25(3.619,-3.15) AN27(3.619,-2.362) AN28(3.619,-1.575) AN30(3.619,-0.787) AN32(3.619,0) AN34(3.619,0.787) AN36(3.619,1.575) AN37(3.619,2.362) AN39(3.619,3.15) AN41(3.619,3.937) AN42(3.619,4.724) AN44(3.619,5.512) AN46(3.619,6.299) U18(-3.619,-6.299) U20(-3.619,-5.512) U22(-3.619,-4.724) U23(-3.619,-3.937) U25(-3.619,-3.15) U27(-3.619,-2.362) U28(-3.619,-1.575) U30(-3.619,-0.787) U32(-3.619,0) U34(-3.619,0.787) U36(-3.619,1.575) U37(-3.619,2.362) U39(-3.619,3.15) U41(-3.619,3.937) U42(-3.619,4.724) U44(-3.619,5.512) U46(-3.619,6.299) V18(-2.896,-6.299) V20(-2.896,-5.512) V22(-2.896,-4.724) V23(-2.896,-3.937) V25(-2.896,-3.15) V27(-2.896,-2.362) V28(-2.896,-1.575) V30(-2.896,-0.787) V32(-2.896,0) V34(-2.896,0.787) V36(-2.896,1.575) V37(-2.896,2.362) V39(-2.896,3.15) V41(-2.896,3.937) V42(-2.896,4.724) V44(-2.896,5.512) V46(-2.896,6.299) Y18(-2.172,-6.299) Y20(-2.172,-5.512) Y22(-2.172,-4.724) Y23(-2.172,-3.937) Y25(-2.172,-3.15) Y27(-2.172,-2.362) Y28(-2.172,-1.575) Y30(-2.172,-0.787) Y32(-2.172,0) Y34(-2.172,0.787) Y36(-2.172,1.575) Y37(-2.172,2.362) Y39(-2.172,3.15) Y41(-2.172,3.937) Y42(-2.172,4.724) Y44(-2.172,5.512) Y46(-2.172,6.299)
  round 0.305 smd: AB5(-1.397,-12.999) AB6(-1.397,-12.288) AB7(-1.397,-11.577) AB9(-1.397,-10.866) AB10(-1.397,-10.154) AB12(-1.397,-9.443) AB13(-1.397,-8.732) AB15(-1.397,-8.021) AB16(-1.397,-7.31) AB48(-1.397,7.31) AB49(-1.397,8.021) AB51(-1.397,8.732) AB52(-1.397,9.443) AB54(-1.397,10.154) AB55(-1.397,10.866) AB57(-1.397,11.577) AB58(-1.397,12.288) AB59(-1.397,12.999) AC5(-0.521,-12.999) AC6(-0.521,-12.288) AC7(-0.521,-11.577) AC9(-0.521,-10.866) AC10(-0.521,-10.154) AC12(-0.521,-9.443) AC13(-0.521,-8.732) AC15(-0.521,-8.021) AC16(-0.521,-7.31) AC48(-0.521,7.31) AC49(-0.521,8.021) AC51(-0.521,8.732) AC52(-0.521,9.443) AC54(-0.521,10.154) AC55(-0.521,10.866) AC57(-0.521,11.577) AC58(-0.521,12.288) AC59(-0.521,12.999) AE5(0,-12.644) AE7(0,-11.932) AE8(0,-11.221) AE10(0,-10.51) AE11(0,-9.799) AE13(0,-9.088) AE14(0,-8.376) AE16(0,-7.665) AE17(0,-6.954) AE47(0,6.954) AE48(0,7.665) AE50(0,8.376) AE51(0,9.088) AE53(0,9.799) AE54(0,10.51) AE56(0,11.221) AE57(0,11.932) AE59(0,12.644) AG5(0.521,-12.999) AG6(0.521,-12.288) AG7(0.521,-11.577) AG9(0.521,-10.866) AG10(0.521,-10.154) AG12(0.521,-9.443) AG13(0.521,-8.732) AG15(0.521,-8.021) AG16(0.521,-7.31) AG48(0.521,7.31) AG49(0.521,8.021) AG51(0.521,8.732) AG52(0.521,9.443) AG54(0.521,10.154) AG55(0.521,10.866) AG57(0.521,11.577) AG58(0.521,12.288) AG59(0.521,12.999) AH5(1.397,-12.999) AH6(1.397,-12.288) AH7(1.397,-11.577) AH9(1.397,-10.866) AH10(1.397,-10.154) AH12(1.397,-9.443) AH13(1.397,-8.732) AH15(1.397,-8.021) AH16(1.397,-7.31) AH48(1.397,7.31) AH49(1.397,8.021) AH51(1.397,8.732) AH52(1.397,9.443) AH54(1.397,10.154) AH55(1.397,10.866) AH57(1.397,11.577) AH58(1.397,12.288) AH59(1.397,12.999) AK5(2.349,-12.999) AK6(2.349,-12.288) AK7(2.349,-11.577) AK9(2.349,-10.866) AK10(2.349,-10.154) AK12(2.349,-9.443) AK13(2.349,-8.732) AK15(2.349,-8.021) AK16(2.349,-7.31) AK48(2.349,7.31) AK49(2.349,8.021) AK51(2.349,8.732) AK52(2.349,9.443) AK54(2.349,10.154) AK55(2.349,10.866) AK57(2.349,11.577) AK58(2.349,12.288) AK59(2.349,12.999) AM5(3.226,-12.999) AM6(3.226,-12.288) AM7(3.226,-11.577) AM9(3.226,-10.866) AM10(3.226,-10.154) AM12(3.226,-9.443) AM13(3.226,-8.732) AM15(3.226,-8.021) AM16(3.226,-7.31) AM48(3.226,7.31) AM49(3.226,8.021) AM51(3.226,8.732) AM52(3.226,9.443) AM54(3.226,10.154) AM55(3.226,10.866) AM57(3.226,11.577) AM58(3.226,12.288) AM59(3.226,12.999) AN5(3.747,-12.644) AN7(3.747,-11.932) AN8(3.747,-11.221) AN10(3.747,-10.51) AN11(3.747,-9.799) AN13(3.747,-9.088) AN14(3.747,-8.376) AN16(3.747,-7.665) AN17(3.747,-6.954) AN47(3.747,6.954) AN48(3.747,7.665) AN50(3.747,8.376) AN51(3.747,9.088) AN53(3.747,9.799) AN54(3.747,10.51) AN56(3.747,11.221) AN57(3.747,11.932) AN59(3.747,12.644) AP5(4.267,-12.999) AP6(4.267,-12.288) AP7(4.267,-11.577) AP9(4.267,-10.866) AP10(4.267,-10.154) AP12(4.267,-9.443) AP13(4.267,-8.732) AP15(4.267,-8.021) AP49(4.267,8.021) AP51(4.267,8.732) AP52(4.267,9.443) AP54(4.267,10.154) AP55(4.267,10.866) AP57(4.267,11.577) AP58(4.267,12.288) AP59(4.267,12.999) AR17(4.432,-7.004) AR19(4.432,-6.096) AR21(4.432,-5.144) AR23(4.432,-4.223) AR25(4.432,-3.27) AR27(4.432,-2.349) AR29(4.432,-1.397) AR30(4.432,-0.476) AR32(4.787,0) AR34(4.432,0.476) AR35(4.432,1.397) AR37(4.432,2.349) AR39(4.432,3.27) AR41(4.432,4.223) AR43(4.432,5.144) AR45(4.432,6.096) AR47(4.432,7.004) AT5(5.144,-12.999) AT6(5.144,-12.288) AT7(5.144,-11.577) AT9(5.144,-10.866) AT10(5.144,-10.154) AT12(5.144,-9.443) AT13(5.144,-8.732) AT16(5.143,-7.626) AT17(5.143,-7.004) AT19(5.143,-6.096) AT21(5.143,-5.144) AT23(5.143,-4.223) AT25(5.143,-3.27) AT27(5.143,-2.349) AT29(5.143,-1.397) AT30(5.143,-0.476) AT34(5.143,0.476) AT35(5.143,1.397) AT37(5.143,2.349) AT39(5.143,3.27) AT41(5.143,4.223) AT43(5.143,5.144) AT45(5.143,6.096) AT47(5.143,7.004) AT48(5.143,7.626) AT51(5.144,8.732) AT52(5.144,9.443) AT54(5.144,10.154) AT55(5.144,10.866) AT57(5.144,11.577) AT58(5.144,12.288) AT59(5.144,12.999) AU32(5.499,0) AV5(6.096,-12.999) AV6(6.096,-12.288) AV7(6.096,-11.577) AV9(6.096,-10.866) AV10(6.096,-10.154) AV12(6.096,-9.443) AV14(5.854,-8.534) AV16(5.854,-7.626) AV17(5.854,-7.004) AV19(5.854,-6.096) AV21(5.854,-5.144) AV23(5.854,-4.223) AV25(5.854,-3.27) AV27(5.854,-2.349) AV29(5.854,-1.397) AV30(5.854,-0.476) AV32(6.21,0) AV34(5.854,0.476) AV35(5.854,1.397) AV37(5.854,2.349) AV39(5.854,3.27) AV41(5.854,4.223) AV43(5.854,5.144) AV45(5.854,6.096) AV47(5.854,7.004) AV48(5.854,7.626) AV50(5.854,8.534) AV52(6.096,9.443) AV54(6.096,10.154) AV55(6.096,10.866) AV57(6.096,11.577) AV58(6.096,12.288) AV59(6.096,12.999) AW14(6.565,-8.534) AW16(6.565,-7.626) AW17(6.565,-7.004) AW19(6.565,-6.096) AW21(6.565,-5.144) AW23(6.565,-4.223) AW25(6.565,-3.27) AW27(6.565,-2.349) AW29(6.565,-1.397) AW30(6.565,-0.476) AW34(6.565,0.476) AW35(6.565,1.397) AW37(6.565,2.349) AW39(6.565,3.27) AW41(6.565,4.223) AW43(6.565,5.144) AW45(6.565,6.096) AW47(6.565,7.004) AW48(6.565,7.626) AW50(6.565,8.534) AY5(7.048,-12.999) AY6(7.048,-12.288) AY7(7.048,-11.577) AY9(7.048,-10.866) AY10(7.048,-10.154) AY32(6.921,0) AY54(7.048,10.154) AY55(7.048,10.866) AY57(7.048,11.577) AY58(7.048,12.288) AY59(7.048,12.999) B7(-10.72,-11.968) BA12(7.277,-9.487) BA14(7.277,-8.534) BA16(7.277,-7.626) BA17(7.277,-7.004) BA19(7.277,-6.096) BA21(7.277,-5.144) BA23(7.277,-4.223) BA25(7.277,-3.27) BA27(7.277,-2.349) BA29(7.277,-1.397) BA30(7.277,-0.476) BA32(7.632,0) BA34(7.277,0.476) BA35(7.277,1.397) BA37(7.277,2.349) BA39(7.277,3.27) BA41(7.277,4.223) BA43(7.277,5.144) BA45(7.277,6.096) BA47(7.277,7.004) BA48(7.277,7.626) BA50(7.277,8.534) BA52(7.277,9.487) BB3(8.001,-13.66) BB5(8.001,-12.999) BB6(8.001,-12.288) BB7(8.001,-11.577) BB10(7.988,-10.439) BB12(7.988,-9.487) BB14(7.988,-8.534) BB16(7.988,-7.626) BB17(7.988,-7.004) BB19(7.988,-6.096) BB21(7.988,-5.144) BB23(7.988,-4.223) BB25(7.988,-3.27) BB27(7.988,-2.349) BB29(7.988,-1.397) BB30(7.988,-0.476) BB34(7.988,0.476) BB35(7.988,1.397) BB37(7.988,2.349) BB39(7.988,3.27) BB41(7.988,4.223) BB43(7.988,5.144) BB45(7.988,6.096) BB47(7.988,7.004) BB48(7.988,7.626) BB50(7.988,8.534) BB52(7.988,9.487) BB54(7.988,10.439) BB57(8.001,11.577) BB58(8.001,12.288) BB59(8.001,12.999) BB61(8.001,13.66) BC32(8.343,0) BD3(8.89,-13.629) BD5(8.89,-12.961) BD6(8.89,-12.288) BD8(8.699,-11.392) BD10(8.699,-10.439) BD12(8.699,-9.487) BD14(8.699,-8.534) BD16(8.699,-7.626) BD17(8.699,-7.004) BD19(8.699,-6.096) BD21(8.699,-5.144) BD23(8.699,-4.223) BD25(8.699,-3.27) BD27(8.699,-2.349) BD29(8.699,-1.397) BD30(8.699,-0.476) BD32(9.055,0) BD34(8.699,0.476) BD35(8.699,1.397) BD37(8.699,2.349) BD39(8.699,3.27) BD41(8.699,4.223) BD43(8.699,5.144) BD45(8.699,6.096) BD47(8.699,7.004) BD48(8.699,7.626) BD50(8.699,8.534) BD52(8.699,9.487) BD54(8.699,10.439) BD56(8.699,11.392) BD58(8.89,12.288) BD59(8.89,12.961) BD61(8.89,13.629) BE8(9.41,-11.392) BE10(9.41,-10.439) BE12(9.41,-9.487) BE14(9.41,-8.534) BE16(9.41,-7.626) BE17(9.41,-7.004) BE19(9.41,-6.096) BE21(9.41,-5.144) BE23(9.41,-4.223) BE25(9.41,-3.27) BE27(9.41,-2.349) BE29(9.41,-1.397) BE30(9.41,-0.476) BE34(9.41,0.476) BE35(9.41,1.397) BE37(9.41,2.349) BE39(9.41,3.27) BE41(9.41,4.223) BE43(9.41,5.144) BE45(9.41,6.096) BE47(9.41,7.004) BE48(9.41,7.626) BE50(9.41,8.534) BE52(9.41,9.487) BE54(9.41,10.439) BE56(9.41,11.392) BF3(9.682,-13.629) BF5(9.682,-12.961) BF6(10.121,-12.344) BF58(10.121,12.344) BF59(9.682,12.961) BF61(9.682,13.629) D4(-10.121,-13.139) D6(-10.121,-12.255) D8(-10.121,-11.392) D58(-10.121,12.344) D59(-9.682,12.961) D61(-9.682,13.629) E3(-9.624,-13.622) E4(-9.474,-13.025) E6(-9.41,-12.255) E8(-9.41,-11.392) E10(-9.41,-10.439) E12(-9.41,-9.487) E14(-9.41,-8.534) E16(-9.41,-7.626) E17(-9.41,-7.004) E19(-9.41,-6.096) E21(-9.41,-5.144) E23(-9.41,-4.223) E25(-9.41,-3.27) E27(-9.41,-2.349) E29(-9.41,-1.397) E30(-9.41,-0.476) E34(-9.41,0.476) E35(-9.41,1.397) E37(-9.41,2.349) E39(-9.41,3.27) E41(-9.41,4.223) E43(-9.41,5.144) E45(-9.41,6.096) E47(-9.41,7.004) E48(-9.41,7.626) E50(-9.41,8.534) E52(-9.41,9.487) E54(-9.41,10.439) E56(-9.41,11.392) F3(-8.7,-13.698) F5(-8.7,-12.999) F6(-8.7,-12.288) F8(-8.699,-11.392) F10(-8.699,-10.439) F12(-8.699,-9.487) F14(-8.699,-8.534) F16(-8.699,-7.626) F17(-8.699,-7.004) F19(-8.699,-6.096) F21(-8.699,-5.144) F23(-8.699,-4.223) F25(-8.699,-3.27) F27(-8.699,-2.349) F29(-8.699,-1.397) F30(-8.699,-0.476) F32(-9.055,0) F34(-8.699,0.476) F35(-8.699,1.397) F37(-8.699,2.349) F39(-8.699,3.27) F41(-8.699,4.223) F43(-8.699,5.144) F45(-8.699,6.096) F47(-8.699,7.004) F48(-8.699,7.626) F50(-8.699,8.534) F52(-8.699,9.487) F54(-8.699,10.439) F56(-8.699,11.392) F58(-8.89,12.288) F59(-8.89,12.961) F61(-8.89,13.629) G32(-8.343,0) H3(-8.02,-13.859) H5(-7.912,-12.999) H6(-7.912,-12.288) H7(-7.912,-11.577) H10(-7.988,-10.439) H12(-7.988,-9.487) H14(-7.988,-8.534) H16(-7.988,-7.626) H17(-7.988,-7.004) H19(-7.988,-6.096) H21(-7.988,-5.144) H23(-7.988,-4.223) H25(-7.988,-3.27) H27(-7.988,-2.349) H29(-7.988,-1.397) H30(-7.988,-0.476) H34(-7.988,0.476) H35(-7.988,1.397) H37(-7.988,2.349) H39(-7.988,3.27) H41(-7.988,4.223) H43(-7.988,5.144) H45(-7.988,6.096) H47(-7.988,7.004) H48(-7.988,7.626) H50(-7.988,8.534) H52(-7.988,9.487) H54(-7.988,10.439) H57(-8.001,11.577) H58(-8.001,12.288) H59(-8.001,12.999) J12(-7.277,-9.487) J14(-7.277,-8.534) J16(-7.277,-7.626) J17(-7.277,-7.004) J19(-7.277,-6.096) J21(-7.277,-5.144) J23(-7.277,-4.223) J25(-7.277,-3.27) J27(-7.277,-2.349) J29(-7.277,-1.397) J30(-7.277,-0.476) J32(-7.632,0) J34(-7.277,0.476) J35(-7.277,1.397) J37(-7.277,2.349) J39(-7.277,3.27) J41(-7.277,4.223) J43(-7.277,5.144) J45(-7.277,6.096) J47(-7.277,7.004) J48(-7.277,7.626) J50(-7.277,8.534) J52(-7.277,9.487) K5(-7.048,-12.999) K6(-7.048,-12.288) K7(-7.048,-11.577) K9(-7.048,-10.866) K10(-7.048,-10.154) K32(-6.921,0) K54(-7.048,10.154) K55(-7.048,10.866) K57(-7.048,11.577) K58(-7.048,12.288) K59(-7.048,12.999) L14(-6.565,-8.534) L16(-6.565,-7.626) L17(-6.565,-7.004) L19(-6.565,-6.096) L21(-6.565,-5.144) L23(-6.565,-4.223) L25(-6.565,-3.27) L27(-6.565,-2.349) L29(-6.565,-1.397) L30(-6.565,-0.476) L34(-6.565,0.476) L35(-6.565,1.397) L37(-6.565,2.349) L39(-6.565,3.27) L41(-6.565,4.223) L43(-6.565,5.144) L45(-6.565,6.096) L47(-6.565,7.004) L48(-6.565,7.626) L50(-6.565,8.534) M5(-6.096,-12.999) M6(-6.096,-12.288) M7(-6.096,-11.577) M9(-6.096,-10.866) M10(-6.096,-10.154) M12(-6.096,-9.443) M14(-5.854,-8.534) M16(-5.854,-7.626) M17(-5.854,-7.004) M19(-5.854,-6.096) M21(-5.854,-5.144) M23(-5.854,-4.223) M25(-5.854,-3.27) M27(-5.854,-2.349) M29(-5.854,-1.397) M30(-5.854,-0.476) M32(-6.21,0) M34(-5.854,0.476) M35(-5.854,1.397) M37(-5.854,2.349) M39(-5.854,3.27) M41(-5.854,4.223) M43(-5.854,5.144) M45(-5.854,6.096) M47(-5.854,7.004) M48(-5.854,7.626) M50(-5.854,8.534) M52(-6.096,9.443) M54(-6.096,10.154) M55(-6.096,10.866) M57(-6.096,11.577) M58(-6.096,12.288) M59(-6.096,12.999) N32(-5.499,0) P5(-5.144,-12.999) P6(-5.144,-12.288) P7(-5.144,-11.577) P9(-5.144,-10.866) P10(-5.144,-10.154) P12(-5.144,-9.443) P13(-5.144,-8.732) P16(-5.143,-7.626) P17(-5.143,-7.004) P19(-5.143,-6.096) P21(-5.143,-5.144) P23(-5.143,-4.223) P25(-5.143,-3.27) P27(-5.143,-2.349) P29(-5.143,-1.397) P30(-5.143,-0.476) P34(-5.143,0.476) P35(-5.143,1.397) P37(-5.143,2.349) P39(-5.143,3.27) P41(-5.143,4.223) P43(-5.143,5.144) P45(-5.143,6.096) P47(-5.143,7.004) P48(-5.143,7.626) P51(-5.144,8.732) P52(-5.144,9.443) P54(-5.144,10.154) P55(-5.144,10.866) P57(-5.144,11.577) P58(-5.144,12.288) P59(-5.144,12.999) R17(-4.432,-7.004) R19(-4.432,-6.096) R21(-4.432,-5.144) R23(-4.432,-4.223) R25(-4.432,-3.27) R27(-4.432,-2.349) R29(-4.432,-1.397) R30(-4.432,-0.476) R32(-4.787,0) R34(-4.432,0.476) R35(-4.432,1.397) R37(-4.432,2.349) R39(-4.432,3.27) R41(-4.432,4.223) R43(-4.432,5.144) R45(-4.432,6.096) R47(-4.432,7.004) T5(-4.267,-12.999) T6(-4.267,-12.288) T7(-4.267,-11.577) T9(-4.267,-10.866) T10(-4.267,-10.154) T12(-4.267,-9.443) T13(-4.267,-8.732) T15(-4.267,-8.021) T49(-4.267,8.021) T51(-4.267,8.732) T52(-4.267,9.443) T54(-4.267,10.154) T55(-4.267,10.866) T57(-4.267,11.577) T58(-4.267,12.288) T59(-4.267,12.999) U5(-3.747,-12.644) U7(-3.747,-11.932) U8(-3.747,-11.221) U10(-3.747,-10.51) U11(-3.747,-9.799) U13(-3.747,-9.088) U14(-3.747,-8.376) U16(-3.747,-7.665) U17(-3.747,-6.954) U47(-3.747,6.954) U48(-3.747,7.665) U50(-3.747,8.376) U51(-3.747,9.088) U53(-3.747,9.799) U54(-3.747,10.51) U56(-3.747,11.221) U57(-3.747,11.932) U59(-3.747,12.644) V5(-3.226,-12.999) V6(-3.226,-12.288) V7(-3.226,-11.577) V9(-3.226,-10.866) V10(-3.226,-10.154) V12(-3.226,-9.443) V13(-3.226,-8.732) V15(-3.226,-8.021) V16(-3.226,-7.31) V48(-3.226,7.31) V49(-3.226,8.021) V51(-3.226,8.732) V52(-3.226,9.443) V54(-3.226,10.154) V55(-3.226,10.866) V57(-3.226,11.577) V58(-3.226,12.288) V59(-3.226,12.999) Y5(-2.349,-12.999) Y6(-2.349,-12.288) Y7(-2.349,-11.577) Y9(-2.349,-10.866) Y10(-2.349,-10.154) Y12(-2.349,-9.443) Y13(-2.349,-8.732) Y15(-2.349,-8.021) Y16(-2.349,-7.31) Y48(-2.349,7.31) Y49(-2.349,8.021) Y51(-2.349,8.732) Y52(-2.349,9.443) Y54(-2.349,10.154) Y55(-2.349,10.866) Y57(-2.349,11.577) Y58(-2.349,12.288) Y59(-2.349,12.999)
